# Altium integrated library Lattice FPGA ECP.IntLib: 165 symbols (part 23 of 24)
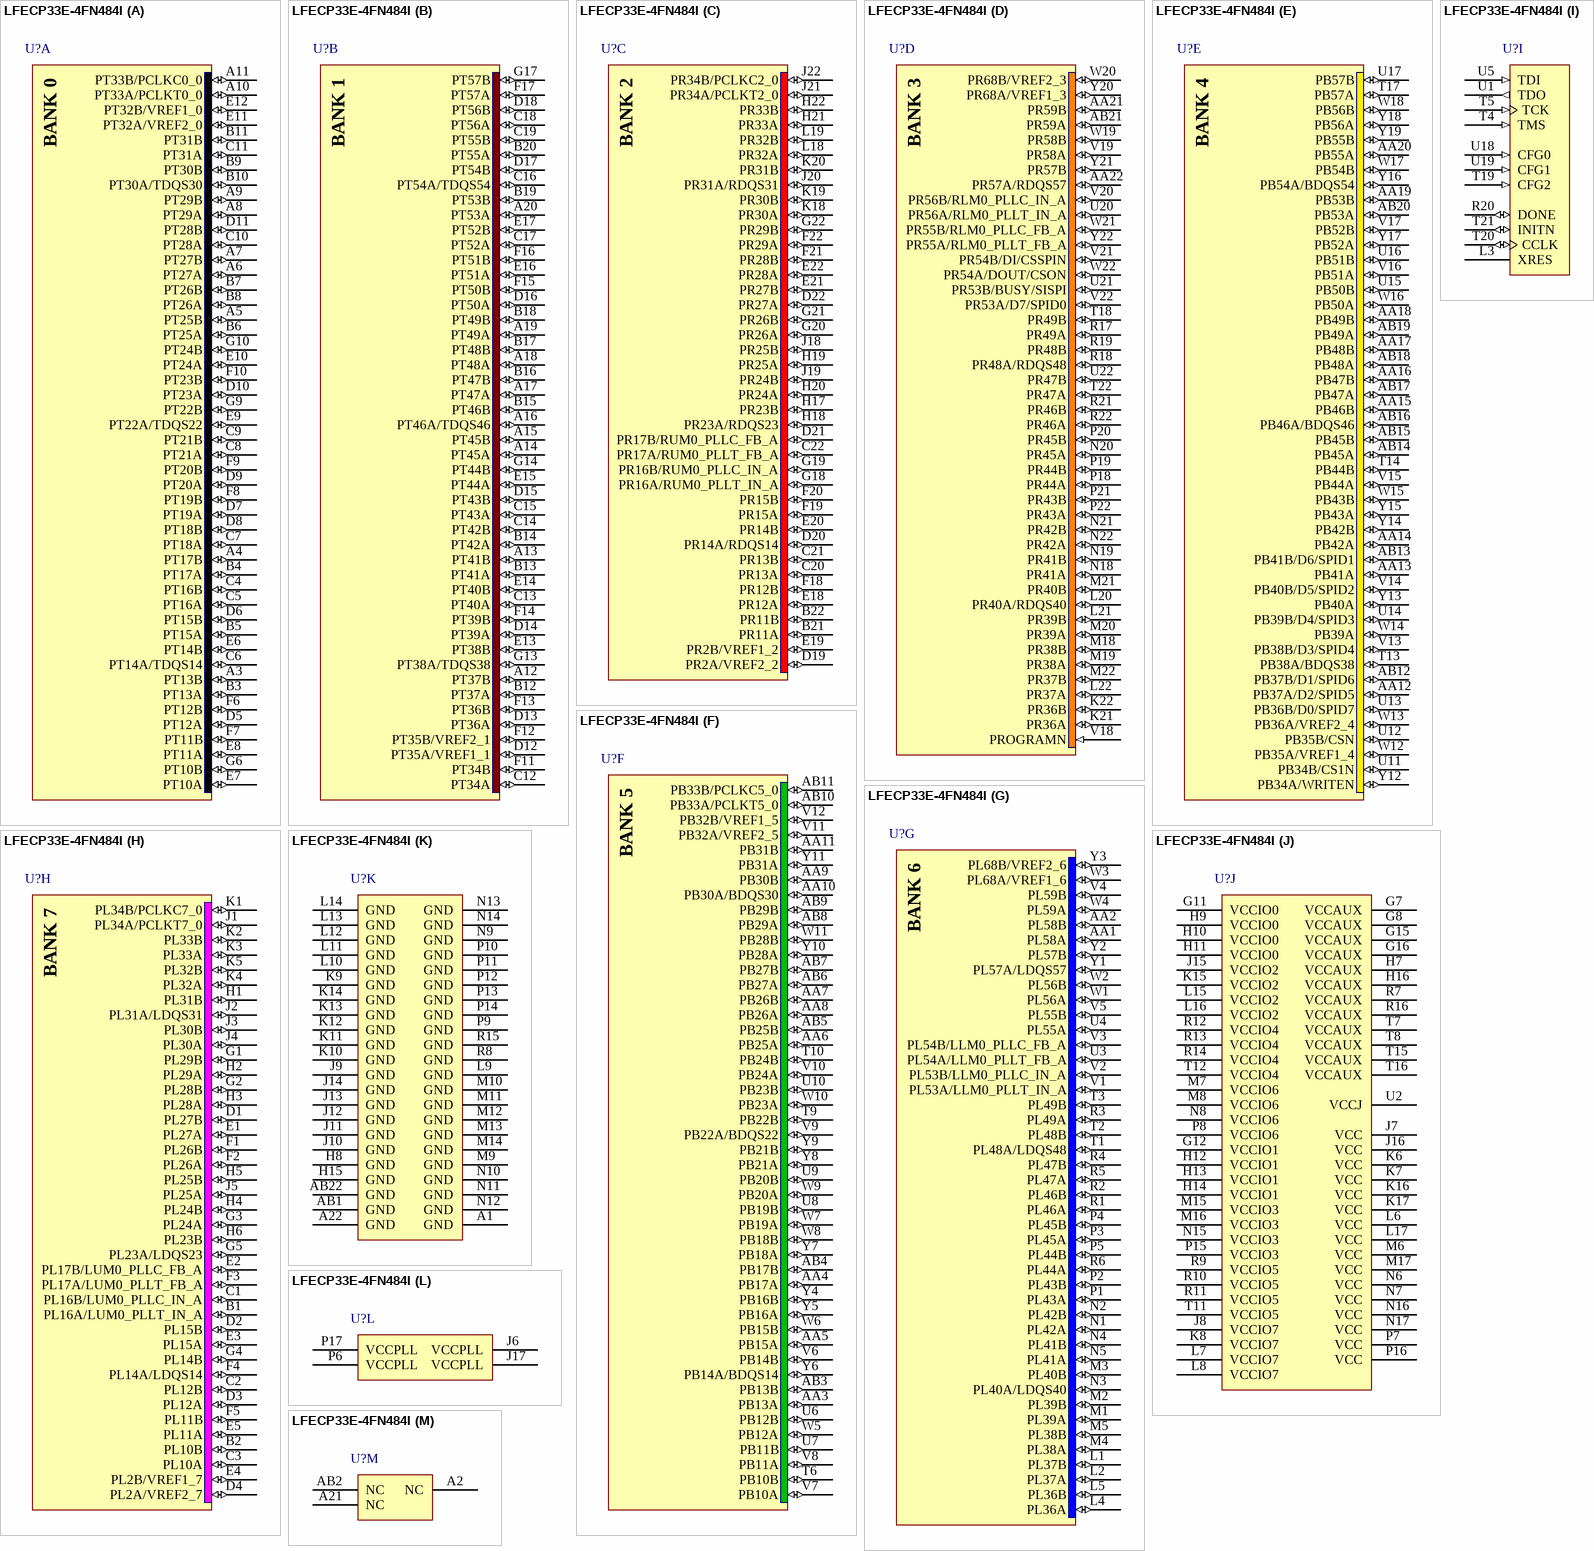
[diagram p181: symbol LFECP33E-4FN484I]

## LFECP33E-4FN484I
designator U?
ECP 1.2V FPGA, 360 I/Os, 4 PLLs, 32.8K LUTs, 8 sysDSP Blocks, 32 18x18 Multipliers, 484-Pin fpBGA, Pb-Free, Speed Grade 4, Industrial Temperature Grade
footprint fpBGA484 (BGA, 484-Leads, Body 23x23mm, Pitch 1mm)
3D model ECP33E-fpBGA484 (484-Ball Fine Pitch Ball Grid Array (fpBGA484))
part A pins: A3 PT13B (io), A4 PT17B (io), A5 PT25B (io), A6 PT27A (io), A7 PT27B (io), A8 PT29A (io), A9 PT29B (io), A10 PT33A/PCLKT0_0 (io), A11 PT33B/PCLKC0_0 (io), B3 PT13A (io), B4 PT17A (io), B5 PT15A (io), B6 PT25A (io), B7 PT26B (io), B8 PT26A (io), B9 PT30B (io), B10 PT30A/TDQS30 (io), B11 PT31B (io), C4 PT16B (io), C5 PT16A (io), C6 PT14A/TDQS14 (io), C7 PT18A (io), C8 PT21A (io), C9 PT21B (io), C10 PT28A (io), C11 PT31A (io), D5 PT12A (io), D6 PT15B (io), D7 PT19A (io), D8 PT18B (io), D9 PT20A (io), D10 PT23A (io), D11 PT28B (io), E6 PT14B (io), E7 PT10A (io), E8 PT11A (io), E9 PT22A/TDQS22 (io), E10 PT24A (io), E11 PT32A/VREF2_0 (io), E12 PT32B/VREF1_0 (io), F6 PT12B (io), F7 PT11B (io), F8 PT19B (io), F9 PT20B (io), F10 PT23B (io), G6 PT10B (io), G9 PT22B (io), G10 PT24B (io)
part B pins: A12 PT37B (io), A13 PT41B (io), A14 PT45A (io), A15 PT45B (io), A16 PT46A/TDQS46 (io), A17 PT47A (io), A18 PT48A (io), A19 PT49A (io), A20 PT53A (io), B12 PT37A (io), B13 PT41A (io), B14 PT42A (io), B15 PT46B (io), B16 PT47B (io), B17 PT48B (io), B18 PT49B (io), B19 PT53B (io), B20 PT55A (io), C12 PT34A (io), C13 PT40A (io), C14 PT42B (io), C15 PT43A (io), C16 PT54A/TDQS54 (io), C17 PT52A (io), C18 PT56A (io), C19 PT55B (io), D12 PT35A/VREF1_1 (io), D13 PT36A (io), D14 PT39A (io), D15 PT43B (io), D16 PT50A (io), D17 PT54B (io), D18 PT56B (io), E13 PT38B (io), E14 PT40B (io), E15 PT44A (io), E16 PT51A (io), E17 PT52B (io), F11 PT34B (io), F12 PT35B/VREF2_1 (io), F13 PT36B (io), F14 PT39B (io), F15 PT50B (io), F16 PT51B (io), F17 PT57A (io), G13 PT38A/TDQS38 (io), G14 PT44B (io), G17 PT57B (io)
part C pins: B21 PR11A (io), B22 PR11B (io), C20 PR13A (io), C21 PR13B (io), C22 PR17A/RUM0_PLLT_FB_A (io), D19 PR2A/VREF2_2 (io), D20 PR14A/RDQS14 (io), D21 PR17B/RUM0_PLLC_FB_A (io), D22 PR27A (io), E18 PR12A (io), E19 PR2B/VREF1_2 (io), E20 PR14B (io), E21 PR27B (io), E22 PR28A (io), F18 PR12B (io), F19 PR15A (io), F20 PR15B (io), F21 PR28B (io), F22 PR29A (io), G18 PR16A/RUM0_PLLT_IN_A (io), G19 PR16B/RUM0_PLLC_IN_A (io), G20 PR26A (io), G21 PR26B (io), G22 PR29B (io), H17 PR23B (io), H18 PR23A/RDQS23 (io), H19 PR25A (io), H20 PR24A (io), H21 PR33A (io), H22 PR33B (io), J18 PR25B (io), J19 PR24B (io), J20 PR31A/RDQS31 (io), J21 PR34A/PCLKT2_0 (io), J22 PR34B/PCLKC2_0 (io), K18 PR30A (io), K19 PR30B (io), K20 PR31B (io), L18 PR32A (io), L19 PR32B (io)
part D pins: AA21 PR59B (io), AA22 PR57A/RDQS57 (io), AB21 PR59A (io), K21 PR36A (io), K22 PR36B (io), L20 PR40A/RDQS40 (io), L21 PR39B (io), L22 PR37A (io), M18 PR38B (io), M19 PR38A (io), M20 PR39A (io), M21 PR40B (io), M22 PR37B (io), N18 PR41A (io), N19 PR41B (io), N20 PR45A (io), N21 PR42B (io), N22 PR42A (io), P18 PR44A (io), P19 PR44B (io), P20 PR45B (io), P21 PR43B (io), P22 PR43A (io), R17 PR49A (io), R18 PR48A/RDQS48 (io), R19 PR48B (io), R21 PR46B (io), R22 PR46A (io), T18 PR49B (io), T22 PR47A (io), U20 PR56A/RLM0_PLLT_IN_A (io), U21 PR53B/BUSY/SISPI (io), U22 PR47B (io), V18 PROGRAMN (in), V19 PR58A (io), V20 PR56B/RLM0_PLLC_IN_A (io), V21 PR54B/DI/CSSPIN (io), V22 PR53A/D7/SPID0 (io), W19 PR58B (io), W20 PR68B/VREF2_3 (io), W21 PR55B/RLM0_PLLC_FB_A (io), W22 PR54A/DOUT/CSON (io), Y20 PR68A/VREF1_3 (io), Y21 PR57B (io), Y22 PR55A/RLM0_PLLT_FB_A (io)
part E pins: AA12 PB37A/D2/SPID5 (io), AA13 PB41A (io), AA14 PB42A (io), AA15 PB46B (io), AA16 PB47B (io), AA17 PB48B (io), AA18 PB49B (io), AA19 PB53B (io), AA20 PB55A (io), AB12 PB37B/D1/SPID6 (io), AB13 PB41B/D6/SPID1 (io), AB14 PB45A (io), AB15 PB45B (io), AB16 PB46A/BDQS46 (io), AB17 PB47A (io), AB18 PB48A (io), AB19 PB49A (io), AB20 PB53A (io), T13 PB38A/BDQS38 (io), T14 PB44B (io), T17 PB57A (io), U11 PB34B/CS1N (io), U12 PB35B/CSN (io), U13 PB36B/D0/SPID7 (io), U14 PB39B/D4/SPID3 (io), U15 PB50B (io), U16 PB51B (io), U17 PB57B (io), V13 PB38B/D3/SPID4 (io), V14 PB40B/D5/SPID2 (io), V15 PB44A (io), V16 PB51A (io), V17 PB52B (io), W12 PB35A/VREF1_4 (io), W13 PB36A/VREF2_4 (io), W14 PB39A (io), W15 PB43B (io), W16 PB50A (io), W17 PB54B (io), W18 PB56B (io), Y12 PB34A/WRITEN (io), Y13 PB40A (io), Y14 PB42B (io), Y15 PB43A (io), Y16 PB54A/BDQS54 (io), Y17 PB52A (io), Y18 PB56A (io), Y19 PB55B (io)
part F pins: AA3 PB13A (io), AA4 PB17A (io), AA5 PB15A (io), AA6 PB25A (io), AA7 PB26B (io), AA8 PB26A (io), AA9 PB30B (io), AA10 PB30A/BDQS30 (io), AA11 PB31B (io), AB3 PB13B (io), AB4 PB17B (io), AB5 PB25B (io), AB6 PB27A (io), AB7 PB27B (io), AB8 PB29A (io), AB9 PB29B (io), AB10 PB33A/PCLKT5_0 (io), AB11 PB33B/PCLKC5_0 (io), T6 PB10B (io), T9 PB22B (io), T10 PB24B (io), U6 PB12B (io), U7 PB11B (io), U8 PB19B (io), U9 PB20B (io), U10 PB23B (io), V6 PB14B (io), V7 PB10A (io), V8 PB11A (io), V9 PB22A/BDQS22 (io), V10 PB24A (io), V11 PB32A/VREF2_5 (io), V12 PB32B/VREF1_5 (io), W5 PB12A (io), W6 PB15B (io), W7 PB19A (io), W8 PB18B (io), W9 PB20A (io), W10 PB23A (io), W11 PB28B (io), Y4 PB16B (io), Y5 PB16A (io), Y6 PB14A/BDQS14 (io), Y7 PB18A (io), Y8 PB21A (io), Y9 PB21B (io), Y10 PB28A (io), Y11 PB31A (io)
part G pins: AA1 PL58A (io), AA2 PL58B (io), L1 PL37B (io), L2 PL37A (io), L4 PL36A (io), L5 PL36B (io), M1 PL39A (io), M2 PL39B (io), M3 PL40B (io), M4 PL38A (io), M5 PL38B (io), N1 PL42A (io), N2 PL42B (io), N3 PL40A/LDQS40 (io), N4 PL41B (io), N5 PL41A (io), P1 PL43A (io), P2 PL43B (io), P3 PL45A (io), P4 PL45B (io), P5 PL44B (io), R1 PL46A (io), R2 PL46B (io), R3 PL49A (io), R4 PL47B (io), R5 PL47A (io), R6 PL44A (io), T1 PL48A/LDQS48 (io), T2 PL48B (io), T3 PL49B (io), U3 PL54A/LLM0_PLLT_FB_A (io), U4 PL55A (io), V1 PL53A/LLM0_PLLT_IN_A (io), V2 PL53B/LLM0_PLLC_IN_A (io), V3 PL54B/LLM0_PLLC_FB_A (io), V4 PL59B (io), V5 PL55B (io), W1 PL56A (io), W2 PL56B (io), W3 PL68A/VREF1_6 (io), W4 PL59A (io), Y1 PL57A/LDQS57 (io), Y2 PL57B (io), Y3 PL68B/VREF2_6 (io)
part H pins: B1 PL16A/LUM0_PLLT_IN_A (io), B2 PL10B (io), C1 PL16B/LUM0_PLLC_IN_A (io), C2 PL12B (io), C3 PL10A (io), D1 PL27B (io), D2 PL15B (io), D3 PL12A (io), D4 PL2A/VREF2_7 (io), E1 PL27A (io), E2 PL17B/LUM0_PLLC_FB_A (io), E3 PL15A (io), E4 PL2B/VREF1_7 (io), E5 PL11A (io), F1 PL26B (io), F2 PL26A (io), F3 PL17A/LUM0_PLLT_FB_A (io), F4 PL14A/LDQS14 (io), F5 PL11B (io), G1 PL29B (io), G2 PL28B (io), G3 PL24A (io), G4 PL14B (io), G5 PL23A/LDQS23 (io), H1 PL31B (io), H2 PL29A (io), H3 PL28A (io), H4 PL24B (io), H5 PL25B (io), H6 PL23B (io), J1 PL34A/PCLKT7_0 (io), J2 PL31A/LDQS31 (io), J3 PL30B (io), J4 PL30A (io), J5 PL25A (io), K1 PL34B/PCLKC7_0 (io), K2 PL33B (io), K3 PL33A (io), K4 PL32A (io), K5 PL32B (io)
part I pins: L3 XRES, R20 DONE (io), T4 TMS (in), T5 TCK (in), T19 CFG2 (in), T20 CCLK (io), T21 INITN (io), U1 TDO (out), U5 TDI (in), U18 CFG0 (in), U19 CFG1 (in)
part J pins: G7 VCCAUX (power), G8 VCCAUX (power), G11 VCCIO0 (power), G12 VCCIO1 (power), G15 VCCAUX (power), G16 VCCAUX (power), H7 VCCAUX (power), H9 VCCIO0 (power), H10 VCCIO0 (power), H11 VCCIO0 (power), H12 VCCIO1 (power), H13 VCCIO1 (power), H14 VCCIO1 (power), H16 VCCAUX (power), J7 VCC (power), J8 VCCIO7 (power), J15 VCCIO2 (power), J16 VCC (power), K6 VCC (power), K7 VCC (power), K8 VCCIO7 (power), K15 VCCIO2 (power), K16 VCC (power), K17 VCC (power), L6 VCC (power), L7 VCCIO7 (power), L8 VCCIO7 (power), L15 VCCIO2 (power), L16 VCCIO2 (power), L17 VCC (power), M6 VCC (power), M7 VCCIO6 (power), M8 VCCIO6 (power), M15 VCCIO3 (power), M16 VCCIO3 (power), M17 VCC (power), N6 VCC (power), N7 VCC (power), N8 VCCIO6 (power), N15 VCCIO3 (power), N16 VCC (power), N17 VCC (power), P7 VCC (power), P8 VCCIO6 (power), P15 VCCIO3 (power), P16 VCC (power), R7 VCCAUX (power), R9 VCCIO5 (power), R10 VCCIO5 (power), R11 VCCIO5 (power), R12 VCCIO4 (power), R13 VCCIO4 (power), R14 VCCIO4 (power), R16 VCCAUX (power), T7 VCCAUX (power), T8 VCCAUX (power), T11 VCCIO5 (power), T12 VCCIO4 (power), T15 VCCAUX (power), T16 VCCAUX (power), U2 VCCJ (power)
part K pins: A1 GND (power), A22 GND (power), AB1 GND (power), AB22 GND (power), H8 GND (power), H15 GND (power), J9 GND (power), J10 GND (power), J11 GND (power), J12 GND (power), J13 GND (power), J14 GND (power), K9 GND (power), K10 GND (power), K11 GND (power), K12 GND (power), K13 GND (power), K14 GND (power), L9 GND (power), L10 GND (power), L11 GND (power), L12 GND (power), L13 GND (power), L14 GND (power), M9 GND (power), M10 GND (power), M11 GND (power), M12 GND (power), M13 GND (power), M14 GND (power), N9 GND (power), N10 GND (power), N11 GND (power), N12 GND (power), N13 GND (power), N14 GND (power), P9 GND (power), P10 GND (power), P11 GND (power), P12 GND (power), P13 GND (power), P14 GND (power), R8 GND (power), R15 GND (power)
part L pins: J6 VCCPLL (power), J17 VCCPLL (power), P6 VCCPLL (power), P17 VCCPLL (power)
part M pins: A2 NC, A21 NC, AB2 NC

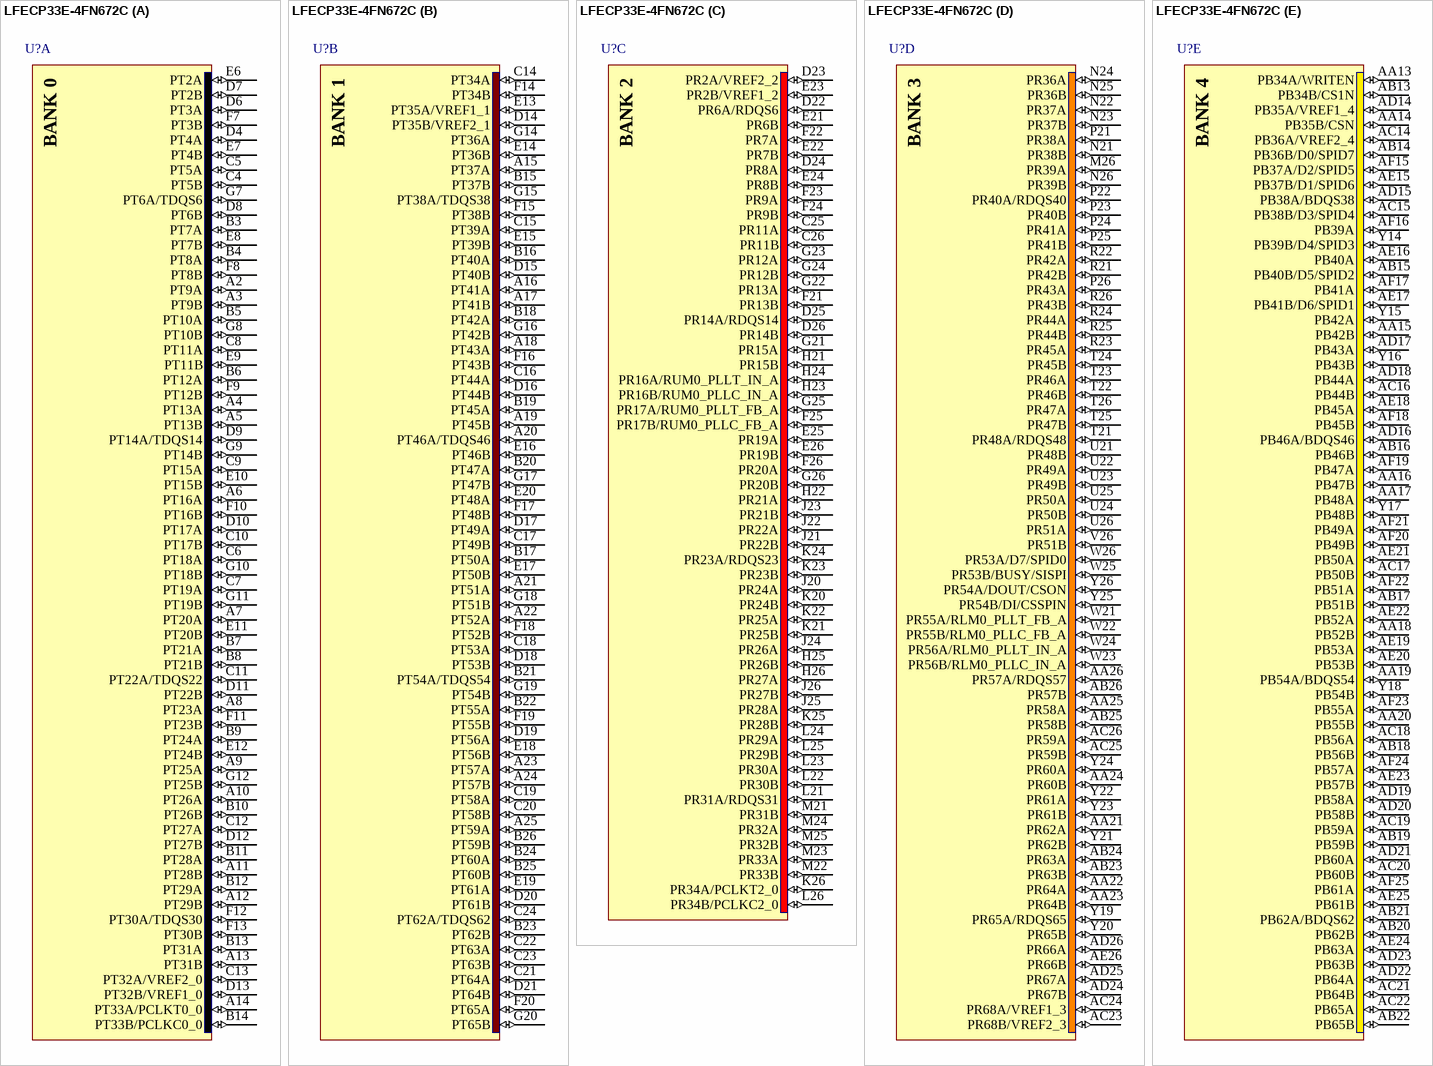
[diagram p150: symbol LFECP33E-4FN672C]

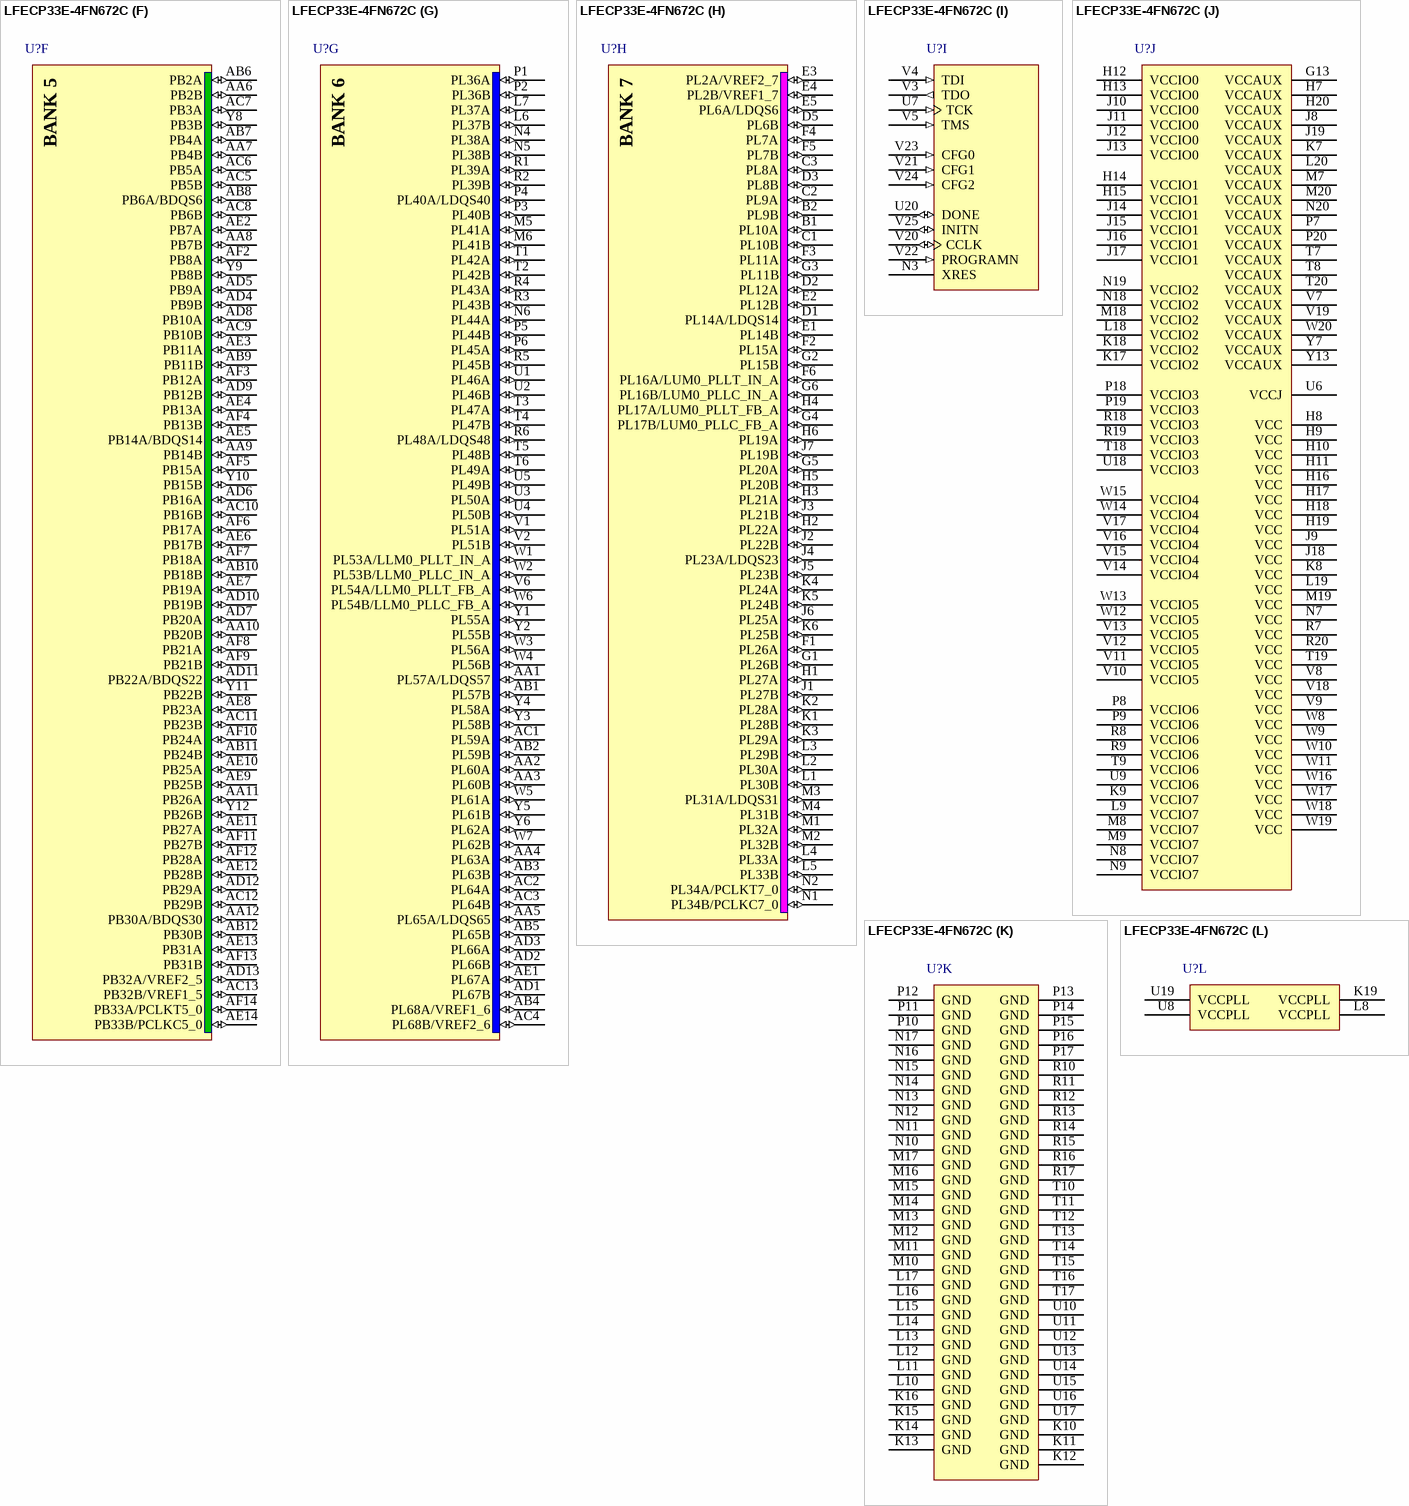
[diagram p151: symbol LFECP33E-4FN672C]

## LFECP33E-4FN672C
designator U?
ECP 1.2V FPGA, 496 I/Os, 4 PLLs, 32.8K LUTs, 8 sysDSP Blocks, 32 18x18 Multipliers, 672-Pin fpBGA, Pb-Free, Speed Grade 4, Commercial Temperature Grade
footprint fpBGA672 (BGA, 672-Leads, Body 27x27mm, Pitch 1mm)
3D model ECP33E-fpBGA672 (672-Ball Fine Pitch Ball Grid Array (fpBGA672))
part A pins: A2 PT9A (io), A3 PT9B (io), A4 PT13A (io), A5 PT13B (io), A6 PT16A (io), A7 PT20A (io), A8 PT23A (io), A9 PT25A (io), A10 PT26A (io), A11 PT28B (io), A12 PT29B (io), A13 PT31B (io), A14 PT33A/PCLKT0_0 (io), B3 PT7A (io), B4 PT8A (io), B5 PT10A (io), B6 PT12A (io), B7 PT21A (io), B8 PT21B (io), B9 PT24A (io), B10 PT26B (io), B11 PT28A (io), B12 PT29A (io), B13 PT31A (io), B14 PT33B/PCLKC0_0 (io), C4 PT5B (io), C5 PT5A (io), C6 PT18A (io), C7 PT19A (io), C8 PT11A (io), C9 PT15A (io), C10 PT17B (io), C11 PT22A/TDQS22 (io), C12 PT27A (io), C13 PT32A/VREF2_0 (io), D4 PT4A (io), D6 PT3A (io), D7 PT2B (io), D8 PT6B (io), D9 PT14A/TDQS14 (io), D10 PT17A (io), D11 PT22B (io), D12 PT27B (io), D13 PT32B/VREF1_0 (io), E6 PT2A (io), E7 PT4B (io), E8 PT7B (io), E9 PT11B (io), E10 PT15B (io), E11 PT20B (io), E12 PT24B (io), F7 PT3B (io), F8 PT8B (io), F9 PT12B (io), F10 PT16B (io), F11 PT23B (io), F12 PT30A/TDQS30 (io), F13 PT30B (io), G7 PT6A/TDQS6 (io), G8 PT10B (io), G9 PT14B (io), G10 PT18B (io), G11 PT19B (io), G12 PT25B (io)
part B pins: A15 PT37A (io), A16 PT41A (io), A17 PT41B (io), A18 PT43A (io), A19 PT45B (io), A20 PT46A/TDQS46 (io), A21 PT51A (io), A22 PT52A (io), A23 PT57A (io), A24 PT57B (io), A25 PT59A (io), B15 PT37B (io), B16 PT40A (io), B17 PT50A (io), B18 PT42A (io), B19 PT45A (io), B20 PT47A (io), B21 PT54A/TDQS54 (io), B22 PT55A (io), B23 PT62B (io), B24 PT60A (io), B25 PT60B (io), B26 PT59B (io), C14 PT34A (io), C15 PT39A (io), C16 PT44A (io), C17 PT49B (io), C18 PT53A (io), C19 PT58A (io), C20 PT58B (io), C21 PT64A (io), C22 PT63A (io), C23 PT63B (io), C24 PT62A/TDQS62 (io), D14 PT35B/VREF2_1 (io), D15 PT40B (io), D16 PT44B (io), D17 PT49A (io), D18 PT53B (io), D19 PT56A (io), D20 PT61B (io), D21 PT64B (io), E13 PT35A/VREF1_1 (io), E14 PT36B (io), E15 PT39B (io), E16 PT46B (io), E17 PT50B (io), E18 PT56B (io), E19 PT61A (io), E20 PT48A (io), F14 PT34B (io), F15 PT38B (io), F16 PT43B (io), F17 PT48B (io), F18 PT52B (io), F19 PT55B (io), F20 PT65A (io), G14 PT36A (io), G15 PT38A/TDQS38 (io), G16 PT42B (io), G17 PT47B (io), G18 PT51B (io), G19 PT54B (io), G20 PT65B (io)
part C pins: C25 PR11A (io), C26 PR11B (io), D22 PR6A/RDQS6 (io), D23 PR2A/VREF2_2 (io), D24 PR8A (io), D25 PR14A/RDQS14 (io), D26 PR14B (io), E21 PR6B (io), E22 PR7B (io), E23 PR2B/VREF1_2 (io), E24 PR8B (io), E25 PR19A (io), E26 PR19B (io), F21 PR13B (io), F22 PR7A (io), F23 PR9A (io), F24 PR9B (io), F25 PR17B/RUM0_PLLC_FB_A (io), F26 PR20A (io), G21 PR15A (io), G22 PR13A (io), G23 PR12A (io), G24 PR12B (io), G25 PR17A/RUM0_PLLT_FB_A (io), G26 PR20B (io), H21 PR15B (io), H22 PR21A (io), H23 PR16B/RUM0_PLLC_IN_A (io), H24 PR16A/RUM0_PLLT_IN_A (io), H25 PR26B (io), H26 PR27A (io), J20 PR24A (io), J21 PR22B (io), J22 PR22A (io), J23 PR21B (io), J24 PR26A (io), J25 PR28A (io), J26 PR27B (io), K20 PR24B (io), K21 PR25B (io), K22 PR25A (io), K23 PR23B (io), K24 PR23A/RDQS23 (io), K25 PR28B (io), K26 PR34A/PCLKT2_0 (io), L21 PR31A/RDQS31 (io), L22 PR30B (io), L23 PR30A (io), L24 PR29A (io), L25 PR29B (io), L26 PR34B/PCLKC2_0 (io), M21 PR31B (io), M22 PR33B (io), M23 PR33A (io), M24 PR32A (io), M25 PR32B (io)
part D pins: AA21 PR62A (io), AA22 PR64A (io), AA23 PR64B (io), AA24 PR60B (io), AA25 PR58A (io), AA26 PR57A/RDQS57 (io), AB23 PR63B (io), AB24 PR63A (io), AB25 PR58B (io), AB26 PR57B (io), AC23 PR68B/VREF2_3 (io), AC24 PR68A/VREF1_3 (io), AC25 PR59B (io), AC26 PR59A (io), AD24 PR67B (io), AD25 PR67A (io), AD26 PR66A (io), AE26 PR66B (io), M26 PR39A (io), N21 PR38B (io), N22 PR37A (io), N23 PR37B (io), N24 PR36A (io), N25 PR36B (io), N26 PR39B (io), P21 PR38A (io), P22 PR40A/RDQS40 (io), P23 PR40B (io), P24 PR41A (io), P25 PR41B (io), P26 PR43A (io), R21 PR42B (io), R22 PR42A (io), R23 PR45A (io), R24 PR44A (io), R25 PR44B (io), R26 PR43B (io), T21 PR48A/RDQS48 (io), T22 PR46B (io), T23 PR46A (io), T24 PR45B (io), T25 PR47B (io), T26 PR47A (io), U21 PR48B (io), U22 PR49A (io), U23 PR49B (io), U24 PR50B (io), U25 PR50A (io), U26 PR51A (io), V26 PR51B (io), W21 PR55A/RLM0_PLLT_FB_A (io), W22 PR55B/RLM0_PLLC_FB_A (io), W23 PR56B/RLM0_PLLC_IN_A (io), W24 PR56A/RLM0_PLLT_IN_A (io), W25 PR53B/BUSY/SISPI (io), W26 PR53A/D7/SPID0 (io), Y19 PR65A/RDQS65 (io), Y20 PR65B (io), Y21 PR62B (io), Y22 PR61A (io), Y23 PR61B (io), Y24 PR60A (io), Y25 PR54B/DI/CSSPIN (io), Y26 PR54A/DOUT/CSON (io)
part E pins: AA13 PB34A/WRITEN (io), AA14 PB35B/CSN (io), AA15 PB42B (io), AA16 PB47B (io), AA17 PB48A (io), AA18 PB52B (io), AA19 PB54A/BDQS54 (io), AA20 PB55B (io), AB13 PB34B/CS1N (io), AB14 PB36B/D0/SPID7 (io), AB15 PB40B/D5/SPID2 (io), AB16 PB46B (io), AB17 PB51B (io), AB18 PB56B (io), AB19 PB59B (io), AB20 PB62B (io), AB21 PB62A/BDQS62 (io), AB22 PB65B (io), AC14 PB36A/VREF2_4 (io), AC15 PB38B/D3/SPID4 (io), AC16 PB44B (io), AC17 PB50B (io), AC18 PB56A (io), AC19 PB59A (io), AC20 PB60B (io), AC21 PB64B (io), AC22 PB65A (io), AD14 PB35A/VREF1_4 (io), AD15 PB38A/BDQS38 (io), AD16 PB46A/BDQS46 (io), AD17 PB43A (io), AD18 PB44A (io), AD19 PB58A (io), AD20 PB58B (io), AD21 PB60A (io), AD22 PB64A (io), AD23 PB63B (io), AE15 PB37B/D1/SPID6 (io), AE16 PB40A (io), AE17 PB41B/D6/SPID1 (io), AE18 PB45A (io), AE19 PB53A (io), AE20 PB53B (io), AE21 PB50A (io), AE22 PB52A (io), AE23 PB57B (io), AE24 PB63A (io), AE25 PB61B (io), AF15 PB37A/D2/SPID5 (io), AF16 PB39A (io), AF17 PB41A (io), AF18 PB45B (io), AF19 PB47A (io), AF20 PB49B (io), AF21 PB49A (io), AF22 PB51A (io), AF23 PB55A (io), AF24 PB57A (io), AF25 PB61A (io), Y14 PB39B/D4/SPID3 (io), Y15 PB42A (io), Y16 PB43B (io), Y17 PB48B (io), Y18 PB54B (io)
part F pins: AA6 PB2B (io), AA7 PB4B (io), AA8 PB7B (io), AA9 PB14B (io), AA10 PB20B (io), AA11 PB26A (io), AA12 PB30A/BDQS30 (io), AB6 PB2A (io), AB7 PB4A (io), AB8 PB6A/BDQS6 (io), AB9 PB11B (io), AB10 PB18B (io), AB11 PB24B (io), AB12 PB30B (io), AC5 PB5B (io), AC6 PB5A (io), AC7 PB3A (io), AC8 PB6B (io), AC9 PB10B (io), AC10 PB16B (io), AC11 PB23B (io), AC12 PB29B (io), AC13 PB32B/VREF1_5 (io), AD4 PB9B (io), AD5 PB9A (io), AD6 PB16A (io), AD7 PB20A (io), AD8 PB10A (io), AD9 PB12B (io), AD10 PB19B (io), AD11 PB22A/BDQS22 (io), AD12 PB29A (io), AD13 PB32A/VREF2_5 (io), AE2 PB7A (io), AE3 PB11A (io), AE4 PB13A (io), AE5 PB14A/BDQS14 (io), AE6 PB17B (io), AE7 PB19A (io), AE8 PB23A (io), AE9 PB25B (io), AE10 PB25A (io), AE11 PB27A (io), AE12 PB28B (io), AE13 PB31A (io), AE14 PB33B/PCLKC5_0 (io), AF2 PB8A (io), AF3 PB12A (io), AF4 PB13B (io), AF5 PB15A (io), AF6 PB17A (io), AF7 PB18A (io), AF8 PB21A (io), AF9 PB21B (io), AF10 PB24A (io), AF11 PB27B (io), AF12 PB28A (io), AF13 PB31B (io), AF14 PB33A/PCLKT5_0 (io), Y8 PB3B (io), Y9 PB8B (io), Y10 PB15B (io), Y11 PB22B (io), Y12 PB26B (io)
part G pins: AA1 PL57A/LDQS57 (io), AA2 PL60A (io), AA3 PL60B (io), AA4 PL63A (io), AA5 PL65A/LDQS65 (io), AB1 PL57B (io), AB2 PL59B (io), AB3 PL63B (io), AB4 PL68A/VREF1_6 (io), AB5 PL65B (io), AC1 PL59A (io), AC2 PL64A (io), AC3 PL64B (io), AC4 PL68B/VREF2_6 (io), AD1 PL67B (io), AD2 PL66B (io), AD3 PL66A (io), AE1 PL67A (io), L6 PL37B (io), L7 PL37A (io), M5 PL41A (io), M6 PL41B (io), N4 PL38A (io), N5 PL38B (io), N6 PL44A (io), P1 PL36A (io), P2 PL36B (io), P3 PL40B (io), P4 PL40A/LDQS40 (io), P5 PL44B (io), P6 PL45A (io), R1 PL39A (io), R2 PL39B (io), R3 PL43B (io), R4 PL43A (io), R5 PL45B (io), R6 PL48A/LDQS48 (io), T1 PL42A (io), T2 PL42B (io), T3 PL47A (io), T4 PL47B (io), T5 PL48B (io), T6 PL49A (io), U1 PL46A (io), U2 PL46B (io), U3 PL50A (io), U4 PL50B (io), U5 PL49B (io), V1 PL51A (io), V2 PL51B (io), V6 PL54A/LLM0_PLLT_FB_A (io), W1 PL53A/LLM0_PLLT_IN_A (io), W2 PL53B/LLM0_PLLC_IN_A (io), W3 PL56A (io), W4 PL56B (io), W5 PL61A (io), W6 PL54B/LLM0_PLLC_FB_A (io), W7 PL62B (io), Y1 PL55A (io), Y2 PL55B (io), Y3 PL58B (io), Y4 PL58A (io), Y5 PL61B (io), Y6 PL62A (io)
part H pins: B1 PL10A (io), B2 PL9B (io), C1 PL10B (io), C2 PL9A (io), C3 PL8A (io), D1 PL14A/LDQS14 (io), D2 PL12A (io), D3 PL8B (io), D5 PL6B (io), E1 PL14B (io), E2 PL12B (io), E3 PL2A/VREF2_7 (io), E4 PL2B/VREF1_7 (io), E5 PL6A/LDQS6 (io), F1 PL26A (io), F2 PL15A (io), F3 PL11A (io), F4 PL7A (io), F5 PL7B (io), F6 PL16A/LUM0_PLLT_IN_A (io), G1 PL26B (io), G2 PL15B (io), G3 PL11B (io), G4 PL17B/LUM0_PLLC_FB_A (io), G5 PL20A (io), G6 PL16B/LUM0_PLLC_IN_A (io), H1 PL27A (io), H2 PL22A (io), H3 PL21A (io), H4 PL17A/LUM0_PLLT_FB_A (io), H5 PL20B (io), H6 PL19A (io), J1 PL27B (io), J2 PL22B (io), J3 PL21B (io), J4 PL23A/LDQS23 (io), J5 PL23B (io), J6 PL25A (io), J7 PL19B (io), K1 PL28B (io), K2 PL28A (io), K3 PL29A (io), K4 PL24A (io), K5 PL24B (io), K6 PL25B (io), L1 PL30B (io), L2 PL30A (io), L3 PL29B (io), L4 PL33A (io), L5 PL33B (io), M1 PL32A (io), M2 PL32B (io), M3 PL31A/LDQS31 (io), M4 PL31B (io), N1 PL34B/PCLKC7_0 (io), N2 PL34A/PCLKT7_0 (io)
part I pins: N3 XRES, U7 TCK (in), U20 DONE (io), V3 TDO (out), V4 TDI (in), V5 TMS (in), V20 CCLK (io), V21 CFG1 (in), V22 PROGRAMN (in), V23 CFG0 (in), V24 CFG2 (in), V25 INITN (io)
part J pins: G13 VCCAUX (power), H7 VCCAUX (power), H8 VCC (power), H9 VCC (power), H10 VCC (power), H11 VCC (power), H12 VCCIO0 (power), H13 VCCIO0 (power), H14 VCCIO1 (power), H15 VCCIO1 (power), H16 VCC (power), H17 VCC (power), H18 VCC (power), H19 VCC (power), H20 VCCAUX (power), J8 VCCAUX (power), J9 VCC (power), J10 VCCIO0 (power), J11 VCCIO0 (power), J12 VCCIO0 (power), J13 VCCIO0 (power), J14 VCCIO1 (power), J15 VCCIO1 (power), J16 VCCIO1 (power), J17 VCCIO1 (power), J18 VCC (power), J19 VCCAUX (power), K7 VCCAUX (power), K8 VCC (power), K9 VCCIO7 (power), K17 VCCIO2 (power), K18 VCCIO2 (power), L9 VCCIO7 (power), L18 VCCIO2 (power), L19 VCC (power), L20 VCCAUX (power), M7 VCCAUX (power), M8 VCCIO7 (power), M9 VCCIO7 (power), M18 VCCIO2 (power), M19 VCC (power), M20 VCCAUX (power), N7 VCC (power), N8 VCCIO7 (power), N9 VCCIO7 (power), N18 VCCIO2 (power), N19 VCCIO2 (power), N20 VCCAUX (power), P7 VCCAUX (power), P8 VCCIO6 (power), P9 VCCIO6 (power), P18 VCCIO3 (power), P19 VCCIO3 (power), P20 VCCAUX (power), R7 VCC (power), R8 VCCIO6 (power), R9 VCCIO6 (power), R18 VCCIO3 (power), R19 VCCIO3 (power), R20 VCC (power), T7 VCCAUX (power), T8 VCCAUX (power), T9 VCCIO6 (power), T18 VCCIO3 (power), T19 VCC (power), T20 VCCAUX (power), U6 VCCJ (power), U9 VCCIO6 (power), U18 VCCIO3 (power), V7 VCCAUX (power), V8 VCC (power), V9 VCC (power), V10 VCCIO5 (power), V11 VCCIO5 (power), V12 VCCIO5 (power), V13 VCCIO5 (power), V14 VCCIO4 (power), V15 VCCIO4 (power), V16 VCCIO4 (power), V17 VCCIO4 (power), V18 VCC (power), V19 VCCAUX (power), W8 VCC (power), W9 VCC (power), W10 VCC (power), W11 VCC (power), W12 VCCIO5 (power), W13 VCCIO5 (power), W14 VCCIO4 (power), W15 VCCIO4 (power), W16 VCC (power), W17 VCC (power), W18 VCC (power), W19 VCC (power), W20 VCCAUX (power), Y7 VCCAUX (power), Y13 VCCAUX (power)
part K pins: K10 GND (power), K11 GND (power), K12 GND (power), K13 GND (power), K14 GND (power), K15 GND (power), K16 GND (power), L10 GND (power), L11 GND (power), L12 GND (power), L13 GND (power), L14 GND (power), L15 GND (power), L16 GND (power), L17 GND (power), M10 GND (power), M11 GND (power), M12 GND (power), M13 GND (power), M14 GND (power), M15 GND (power), M16 GND (power), M17 GND (power), N10 GND (power), N11 GND (power), N12 GND (power), N13 GND (power), N14 GND (power), N15 GND (power), N16 GND (power), N17 GND (power), P10 GND (power), P11 GND (power), P12 GND (power), P13 GND (power), P14 GND (power), P15 GND (power), P16 GND (power), P17 GND (power), R10 GND (power), R11 GND (power), R12 GND (power), R13 GND (power), R14 GND (power), R15 GND (power), R16 GND (power), R17 GND (power), T10 GND (power), T11 GND (power), T12 GND (power), T13 GND (power), T14 GND (power), T15 GND (power), T16 GND (power), T17 GND (power), U10 GND (power), U11 GND (power), U12 GND (power), U13 GND (power), U14 GND (power), U15 GND (power), U16 GND (power), U17 GND (power)
part L pins: K19 VCCPLL (power), L8 VCCPLL (power), U8 VCCPLL (power), U19 VCCPLL (power)

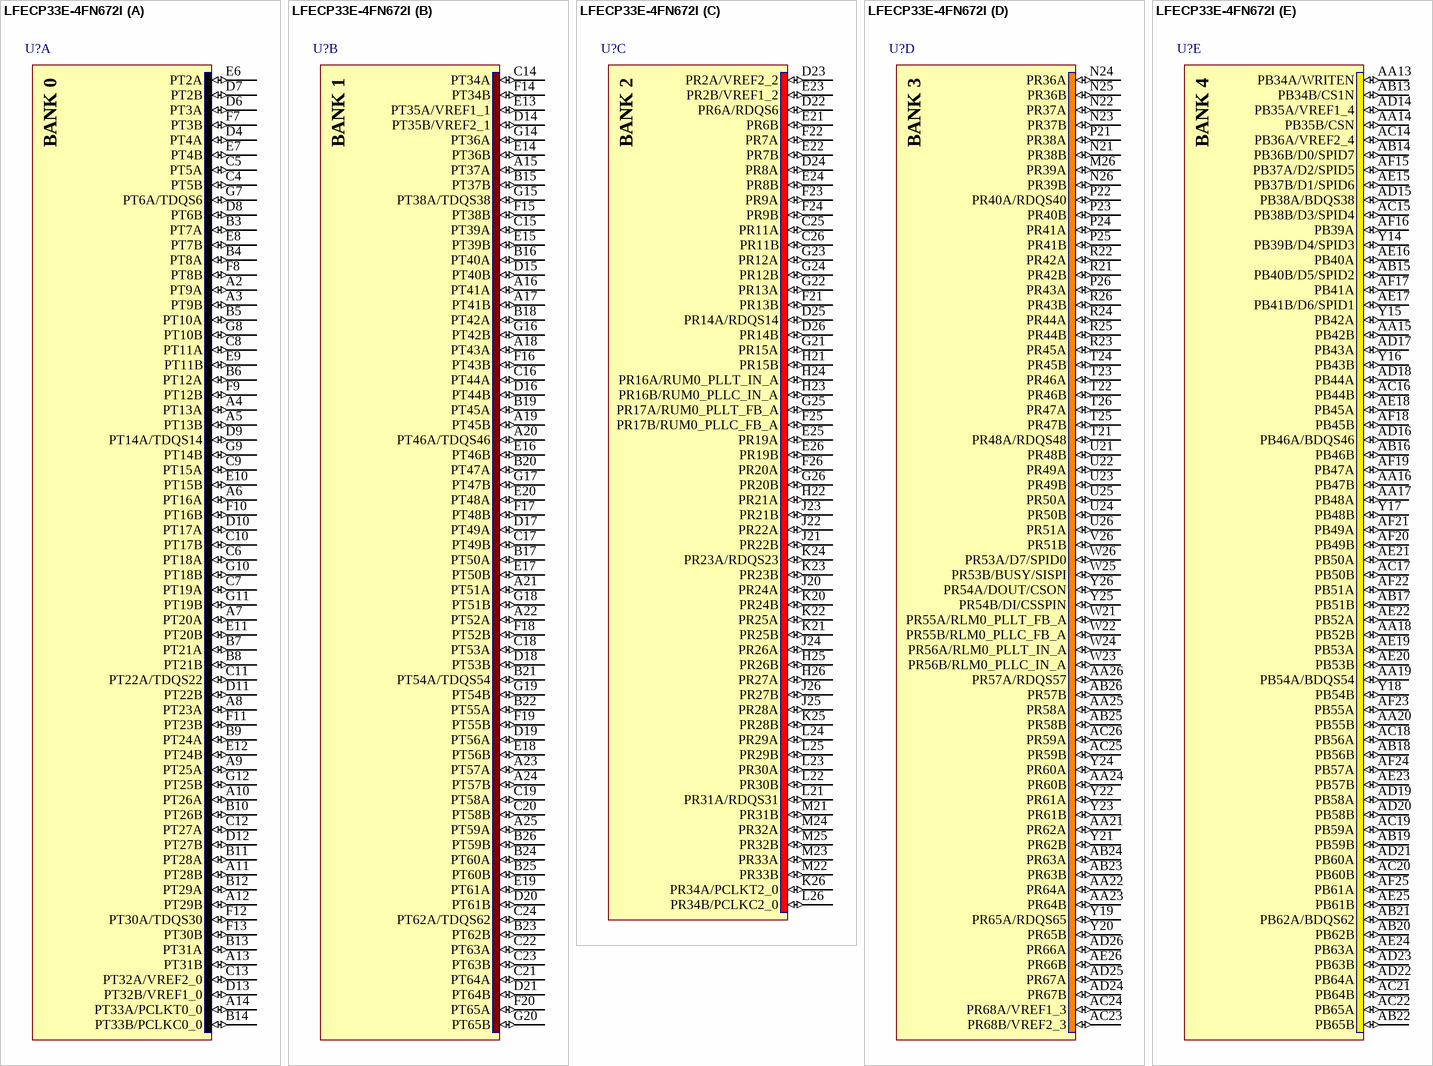
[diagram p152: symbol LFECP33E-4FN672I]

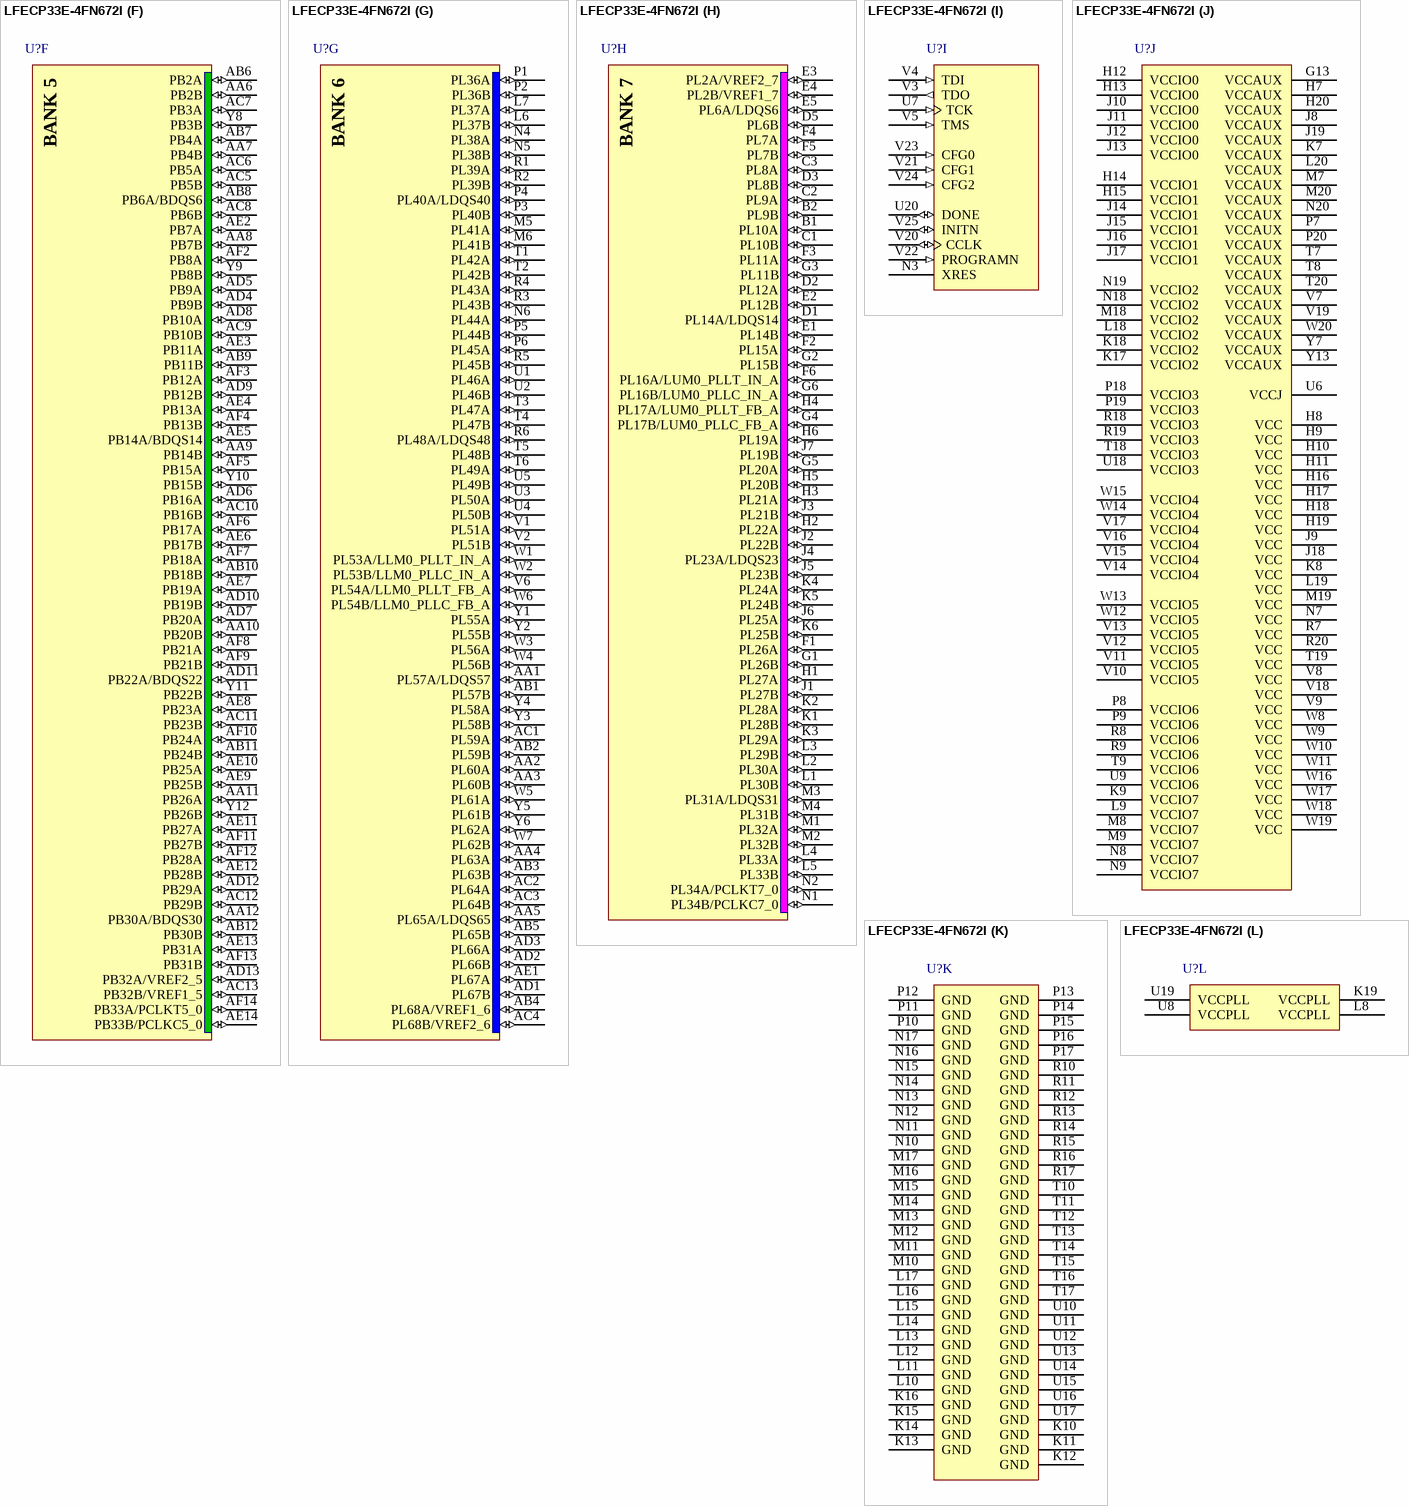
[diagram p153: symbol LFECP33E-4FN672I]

## LFECP33E-4FN672I
designator U?
ECP 1.2V FPGA, 496 I/Os, 4 PLLs, 32.8K LUTs, 8 sysDSP Blocks, 32 18x18 Multipliers, 672-Pin fpBGA, Pb-Free, Speed Grade 4, Industrial Temperature Grade
footprint fpBGA672 (BGA, 672-Leads, Body 27x27mm, Pitch 1mm)
3D model ECP33E-fpBGA672 (672-Ball Fine Pitch Ball Grid Array (fpBGA672))
part A pins: A2 PT9A (io), A3 PT9B (io), A4 PT13A (io), A5 PT13B (io), A6 PT16A (io), A7 PT20A (io), A8 PT23A (io), A9 PT25A (io), A10 PT26A (io), A11 PT28B (io), A12 PT29B (io), A13 PT31B (io), A14 PT33A/PCLKT0_0 (io), B3 PT7A (io), B4 PT8A (io), B5 PT10A (io), B6 PT12A (io), B7 PT21A (io), B8 PT21B (io), B9 PT24A (io), B10 PT26B (io), B11 PT28A (io), B12 PT29A (io), B13 PT31A (io), B14 PT33B/PCLKC0_0 (io), C4 PT5B (io), C5 PT5A (io), C6 PT18A (io), C7 PT19A (io), C8 PT11A (io), C9 PT15A (io), C10 PT17B (io), C11 PT22A/TDQS22 (io), C12 PT27A (io), C13 PT32A/VREF2_0 (io), D4 PT4A (io), D6 PT3A (io), D7 PT2B (io), D8 PT6B (io), D9 PT14A/TDQS14 (io), D10 PT17A (io), D11 PT22B (io), D12 PT27B (io), D13 PT32B/VREF1_0 (io), E6 PT2A (io), E7 PT4B (io), E8 PT7B (io), E9 PT11B (io), E10 PT15B (io), E11 PT20B (io), E12 PT24B (io), F7 PT3B (io), F8 PT8B (io), F9 PT12B (io), F10 PT16B (io), F11 PT23B (io), F12 PT30A/TDQS30 (io), F13 PT30B (io), G7 PT6A/TDQS6 (io), G8 PT10B (io), G9 PT14B (io), G10 PT18B (io), G11 PT19B (io), G12 PT25B (io)
part B pins: A15 PT37A (io), A16 PT41A (io), A17 PT41B (io), A18 PT43A (io), A19 PT45B (io), A20 PT46A/TDQS46 (io), A21 PT51A (io), A22 PT52A (io), A23 PT57A (io), A24 PT57B (io), A25 PT59A (io), B15 PT37B (io), B16 PT40A (io), B17 PT50A (io), B18 PT42A (io), B19 PT45A (io), B20 PT47A (io), B21 PT54A/TDQS54 (io), B22 PT55A (io), B23 PT62B (io), B24 PT60A (io), B25 PT60B (io), B26 PT59B (io), C14 PT34A (io), C15 PT39A (io), C16 PT44A (io), C17 PT49B (io), C18 PT53A (io), C19 PT58A (io), C20 PT58B (io), C21 PT64A (io), C22 PT63A (io), C23 PT63B (io), C24 PT62A/TDQS62 (io), D14 PT35B/VREF2_1 (io), D15 PT40B (io), D16 PT44B (io), D17 PT49A (io), D18 PT53B (io), D19 PT56A (io), D20 PT61B (io), D21 PT64B (io), E13 PT35A/VREF1_1 (io), E14 PT36B (io), E15 PT39B (io), E16 PT46B (io), E17 PT50B (io), E18 PT56B (io), E19 PT61A (io), E20 PT48A (io), F14 PT34B (io), F15 PT38B (io), F16 PT43B (io), F17 PT48B (io), F18 PT52B (io), F19 PT55B (io), F20 PT65A (io), G14 PT36A (io), G15 PT38A/TDQS38 (io), G16 PT42B (io), G17 PT47B (io), G18 PT51B (io), G19 PT54B (io), G20 PT65B (io)
part C pins: C25 PR11A (io), C26 PR11B (io), D22 PR6A/RDQS6 (io), D23 PR2A/VREF2_2 (io), D24 PR8A (io), D25 PR14A/RDQS14 (io), D26 PR14B (io), E21 PR6B (io), E22 PR7B (io), E23 PR2B/VREF1_2 (io), E24 PR8B (io), E25 PR19A (io), E26 PR19B (io), F21 PR13B (io), F22 PR7A (io), F23 PR9A (io), F24 PR9B (io), F25 PR17B/RUM0_PLLC_FB_A (io), F26 PR20A (io), G21 PR15A (io), G22 PR13A (io), G23 PR12A (io), G24 PR12B (io), G25 PR17A/RUM0_PLLT_FB_A (io), G26 PR20B (io), H21 PR15B (io), H22 PR21A (io), H23 PR16B/RUM0_PLLC_IN_A (io), H24 PR16A/RUM0_PLLT_IN_A (io), H25 PR26B (io), H26 PR27A (io), J20 PR24A (io), J21 PR22B (io), J22 PR22A (io), J23 PR21B (io), J24 PR26A (io), J25 PR28A (io), J26 PR27B (io), K20 PR24B (io), K21 PR25B (io), K22 PR25A (io), K23 PR23B (io), K24 PR23A/RDQS23 (io), K25 PR28B (io), K26 PR34A/PCLKT2_0 (io), L21 PR31A/RDQS31 (io), L22 PR30B (io), L23 PR30A (io), L24 PR29A (io), L25 PR29B (io), L26 PR34B/PCLKC2_0 (io), M21 PR31B (io), M22 PR33B (io), M23 PR33A (io), M24 PR32A (io), M25 PR32B (io)
part D pins: AA21 PR62A (io), AA22 PR64A (io), AA23 PR64B (io), AA24 PR60B (io), AA25 PR58A (io), AA26 PR57A/RDQS57 (io), AB23 PR63B (io), AB24 PR63A (io), AB25 PR58B (io), AB26 PR57B (io), AC23 PR68B/VREF2_3 (io), AC24 PR68A/VREF1_3 (io), AC25 PR59B (io), AC26 PR59A (io), AD24 PR67B (io), AD25 PR67A (io), AD26 PR66A (io), AE26 PR66B (io), M26 PR39A (io), N21 PR38B (io), N22 PR37A (io), N23 PR37B (io), N24 PR36A (io), N25 PR36B (io), N26 PR39B (io), P21 PR38A (io), P22 PR40A/RDQS40 (io), P23 PR40B (io), P24 PR41A (io), P25 PR41B (io), P26 PR43A (io), R21 PR42B (io), R22 PR42A (io), R23 PR45A (io), R24 PR44A (io), R25 PR44B (io), R26 PR43B (io), T21 PR48A/RDQS48 (io), T22 PR46B (io), T23 PR46A (io), T24 PR45B (io), T25 PR47B (io), T26 PR47A (io), U21 PR48B (io), U22 PR49A (io), U23 PR49B (io), U24 PR50B (io), U25 PR50A (io), U26 PR51A (io), V26 PR51B (io), W21 PR55A/RLM0_PLLT_FB_A (io), W22 PR55B/RLM0_PLLC_FB_A (io), W23 PR56B/RLM0_PLLC_IN_A (io), W24 PR56A/RLM0_PLLT_IN_A (io), W25 PR53B/BUSY/SISPI (io), W26 PR53A/D7/SPID0 (io), Y19 PR65A/RDQS65 (io), Y20 PR65B (io), Y21 PR62B (io), Y22 PR61A (io), Y23 PR61B (io), Y24 PR60A (io), Y25 PR54B/DI/CSSPIN (io), Y26 PR54A/DOUT/CSON (io)
part E pins: AA13 PB34A/WRITEN (io), AA14 PB35B/CSN (io), AA15 PB42B (io), AA16 PB47B (io), AA17 PB48A (io), AA18 PB52B (io), AA19 PB54A/BDQS54 (io), AA20 PB55B (io), AB13 PB34B/CS1N (io), AB14 PB36B/D0/SPID7 (io), AB15 PB40B/D5/SPID2 (io), AB16 PB46B (io), AB17 PB51B (io), AB18 PB56B (io), AB19 PB59B (io), AB20 PB62B (io), AB21 PB62A/BDQS62 (io), AB22 PB65B (io), AC14 PB36A/VREF2_4 (io), AC15 PB38B/D3/SPID4 (io), AC16 PB44B (io), AC17 PB50B (io), AC18 PB56A (io), AC19 PB59A (io), AC20 PB60B (io), AC21 PB64B (io), AC22 PB65A (io), AD14 PB35A/VREF1_4 (io), AD15 PB38A/BDQS38 (io), AD16 PB46A/BDQS46 (io), AD17 PB43A (io), AD18 PB44A (io), AD19 PB58A (io), AD20 PB58B (io), AD21 PB60A (io), AD22 PB64A (io), AD23 PB63B (io), AE15 PB37B/D1/SPID6 (io), AE16 PB40A (io), AE17 PB41B/D6/SPID1 (io), AE18 PB45A (io), AE19 PB53A (io), AE20 PB53B (io), AE21 PB50A (io), AE22 PB52A (io), AE23 PB57B (io), AE24 PB63A (io), AE25 PB61B (io), AF15 PB37A/D2/SPID5 (io), AF16 PB39A (io), AF17 PB41A (io), AF18 PB45B (io), AF19 PB47A (io), AF20 PB49B (io), AF21 PB49A (io), AF22 PB51A (io), AF23 PB55A (io), AF24 PB57A (io), AF25 PB61A (io), Y14 PB39B/D4/SPID3 (io), Y15 PB42A (io), Y16 PB43B (io), Y17 PB48B (io), Y18 PB54B (io)
part F pins: AA6 PB2B (io), AA7 PB4B (io), AA8 PB7B (io), AA9 PB14B (io), AA10 PB20B (io), AA11 PB26A (io), AA12 PB30A/BDQS30 (io), AB6 PB2A (io), AB7 PB4A (io), AB8 PB6A/BDQS6 (io), AB9 PB11B (io), AB10 PB18B (io), AB11 PB24B (io), AB12 PB30B (io), AC5 PB5B (io), AC6 PB5A (io), AC7 PB3A (io), AC8 PB6B (io), AC9 PB10B (io), AC10 PB16B (io), AC11 PB23B (io), AC12 PB29B (io), AC13 PB32B/VREF1_5 (io), AD4 PB9B (io), AD5 PB9A (io), AD6 PB16A (io), AD7 PB20A (io), AD8 PB10A (io), AD9 PB12B (io), AD10 PB19B (io), AD11 PB22A/BDQS22 (io), AD12 PB29A (io), AD13 PB32A/VREF2_5 (io), AE2 PB7A (io), AE3 PB11A (io), AE4 PB13A (io), AE5 PB14A/BDQS14 (io), AE6 PB17B (io), AE7 PB19A (io), AE8 PB23A (io), AE9 PB25B (io), AE10 PB25A (io), AE11 PB27A (io), AE12 PB28B (io), AE13 PB31A (io), AE14 PB33B/PCLKC5_0 (io), AF2 PB8A (io), AF3 PB12A (io), AF4 PB13B (io), AF5 PB15A (io), AF6 PB17A (io), AF7 PB18A (io), AF8 PB21A (io), AF9 PB21B (io), AF10 PB24A (io), AF11 PB27B (io), AF12 PB28A (io), AF13 PB31B (io), AF14 PB33A/PCLKT5_0 (io), Y8 PB3B (io), Y9 PB8B (io), Y10 PB15B (io), Y11 PB22B (io), Y12 PB26B (io)
part G pins: AA1 PL57A/LDQS57 (io), AA2 PL60A (io), AA3 PL60B (io), AA4 PL63A (io), AA5 PL65A/LDQS65 (io), AB1 PL57B (io), AB2 PL59B (io), AB3 PL63B (io), AB4 PL68A/VREF1_6 (io), AB5 PL65B (io), AC1 PL59A (io), AC2 PL64A (io), AC3 PL64B (io), AC4 PL68B/VREF2_6 (io), AD1 PL67B (io), AD2 PL66B (io), AD3 PL66A (io), AE1 PL67A (io), L6 PL37B (io), L7 PL37A (io), M5 PL41A (io), M6 PL41B (io), N4 PL38A (io), N5 PL38B (io), N6 PL44A (io), P1 PL36A (io), P2 PL36B (io), P3 PL40B (io), P4 PL40A/LDQS40 (io), P5 PL44B (io), P6 PL45A (io), R1 PL39A (io), R2 PL39B (io), R3 PL43B (io), R4 PL43A (io), R5 PL45B (io), R6 PL48A/LDQS48 (io), T1 PL42A (io), T2 PL42B (io), T3 PL47A (io), T4 PL47B (io), T5 PL48B (io), T6 PL49A (io), U1 PL46A (io), U2 PL46B (io), U3 PL50A (io), U4 PL50B (io), U5 PL49B (io), V1 PL51A (io), V2 PL51B (io), V6 PL54A/LLM0_PLLT_FB_A (io), W1 PL53A/LLM0_PLLT_IN_A (io), W2 PL53B/LLM0_PLLC_IN_A (io), W3 PL56A (io), W4 PL56B (io), W5 PL61A (io), W6 PL54B/LLM0_PLLC_FB_A (io), W7 PL62B (io), Y1 PL55A (io), Y2 PL55B (io), Y3 PL58B (io), Y4 PL58A (io), Y5 PL61B (io), Y6 PL62A (io)
part H pins: B1 PL10A (io), B2 PL9B (io), C1 PL10B (io), C2 PL9A (io), C3 PL8A (io), D1 PL14A/LDQS14 (io), D2 PL12A (io), D3 PL8B (io), D5 PL6B (io), E1 PL14B (io), E2 PL12B (io), E3 PL2A/VREF2_7 (io), E4 PL2B/VREF1_7 (io), E5 PL6A/LDQS6 (io), F1 PL26A (io), F2 PL15A (io), F3 PL11A (io), F4 PL7A (io), F5 PL7B (io), F6 PL16A/LUM0_PLLT_IN_A (io), G1 PL26B (io), G2 PL15B (io), G3 PL11B (io), G4 PL17B/LUM0_PLLC_FB_A (io), G5 PL20A (io), G6 PL16B/LUM0_PLLC_IN_A (io), H1 PL27A (io), H2 PL22A (io), H3 PL21A (io), H4 PL17A/LUM0_PLLT_FB_A (io), H5 PL20B (io), H6 PL19A (io), J1 PL27B (io), J2 PL22B (io), J3 PL21B (io), J4 PL23A/LDQS23 (io), J5 PL23B (io), J6 PL25A (io), J7 PL19B (io), K1 PL28B (io), K2 PL28A (io), K3 PL29A (io), K4 PL24A (io), K5 PL24B (io), K6 PL25B (io), L1 PL30B (io), L2 PL30A (io), L3 PL29B (io), L4 PL33A (io), L5 PL33B (io), M1 PL32A (io), M2 PL32B (io), M3 PL31A/LDQS31 (io), M4 PL31B (io), N1 PL34B/PCLKC7_0 (io), N2 PL34A/PCLKT7_0 (io)
part I pins: N3 XRES, U7 TCK (in), U20 DONE (io), V3 TDO (out), V4 TDI (in), V5 TMS (in), V20 CCLK (io), V21 CFG1 (in), V22 PROGRAMN (in), V23 CFG0 (in), V24 CFG2 (in), V25 INITN (io)
part J pins: G13 VCCAUX (power), H7 VCCAUX (power), H8 VCC (power), H9 VCC (power), H10 VCC (power), H11 VCC (power), H12 VCCIO0 (power), H13 VCCIO0 (power), H14 VCCIO1 (power), H15 VCCIO1 (power), H16 VCC (power), H17 VCC (power), H18 VCC (power), H19 VCC (power), H20 VCCAUX (power), J8 VCCAUX (power), J9 VCC (power), J10 VCCIO0 (power), J11 VCCIO0 (power), J12 VCCIO0 (power), J13 VCCIO0 (power), J14 VCCIO1 (power), J15 VCCIO1 (power), J16 VCCIO1 (power), J17 VCCIO1 (power), J18 VCC (power), J19 VCCAUX (power), K7 VCCAUX (power), K8 VCC (power), K9 VCCIO7 (power), K17 VCCIO2 (power), K18 VCCIO2 (power), L9 VCCIO7 (power), L18 VCCIO2 (power), L19 VCC (power), L20 VCCAUX (power), M7 VCCAUX (power), M8 VCCIO7 (power), M9 VCCIO7 (power), M18 VCCIO2 (power), M19 VCC (power), M20 VCCAUX (power), N7 VCC (power), N8 VCCIO7 (power), N9 VCCIO7 (power), N18 VCCIO2 (power), N19 VCCIO2 (power), N20 VCCAUX (power), P7 VCCAUX (power), P8 VCCIO6 (power), P9 VCCIO6 (power), P18 VCCIO3 (power), P19 VCCIO3 (power), P20 VCCAUX (power), R7 VCC (power), R8 VCCIO6 (power), R9 VCCIO6 (power), R18 VCCIO3 (power), R19 VCCIO3 (power), R20 VCC (power), T7 VCCAUX (power), T8 VCCAUX (power), T9 VCCIO6 (power), T18 VCCIO3 (power), T19 VCC (power), T20 VCCAUX (power), U6 VCCJ (power), U9 VCCIO6 (power), U18 VCCIO3 (power), V7 VCCAUX (power), V8 VCC (power), V9 VCC (power), V10 VCCIO5 (power), V11 VCCIO5 (power), V12 VCCIO5 (power), V13 VCCIO5 (power), V14 VCCIO4 (power), V15 VCCIO4 (power), V16 VCCIO4 (power), V17 VCCIO4 (power), V18 VCC (power), V19 VCCAUX (power), W8 VCC (power), W9 VCC (power), W10 VCC (power), W11 VCC (power), W12 VCCIO5 (power), W13 VCCIO5 (power), W14 VCCIO4 (power), W15 VCCIO4 (power), W16 VCC (power), W17 VCC (power), W18 VCC (power), W19 VCC (power), W20 VCCAUX (power), Y7 VCCAUX (power), Y13 VCCAUX (power)
part K pins: K10 GND (power), K11 GND (power), K12 GND (power), K13 GND (power), K14 GND (power), K15 GND (power), K16 GND (power), L10 GND (power), L11 GND (power), L12 GND (power), L13 GND (power), L14 GND (power), L15 GND (power), L16 GND (power), L17 GND (power), M10 GND (power), M11 GND (power), M12 GND (power), M13 GND (power), M14 GND (power), M15 GND (power), M16 GND (power), M17 GND (power), N10 GND (power), N11 GND (power), N12 GND (power), N13 GND (power), N14 GND (power), N15 GND (power), N16 GND (power), N17 GND (power), P10 GND (power), P11 GND (power), P12 GND (power), P13 GND (power), P14 GND (power), P15 GND (power), P16 GND (power), P17 GND (power), R10 GND (power), R11 GND (power), R12 GND (power), R13 GND (power), R14 GND (power), R15 GND (power), R16 GND (power), R17 GND (power), T10 GND (power), T11 GND (power), T12 GND (power), T13 GND (power), T14 GND (power), T15 GND (power), T16 GND (power), T17 GND (power), U10 GND (power), U11 GND (power), U12 GND (power), U13 GND (power), U14 GND (power), U15 GND (power), U16 GND (power), U17 GND (power)
part L pins: K19 VCCPLL (power), L8 VCCPLL (power), U8 VCCPLL (power), U19 VCCPLL (power)

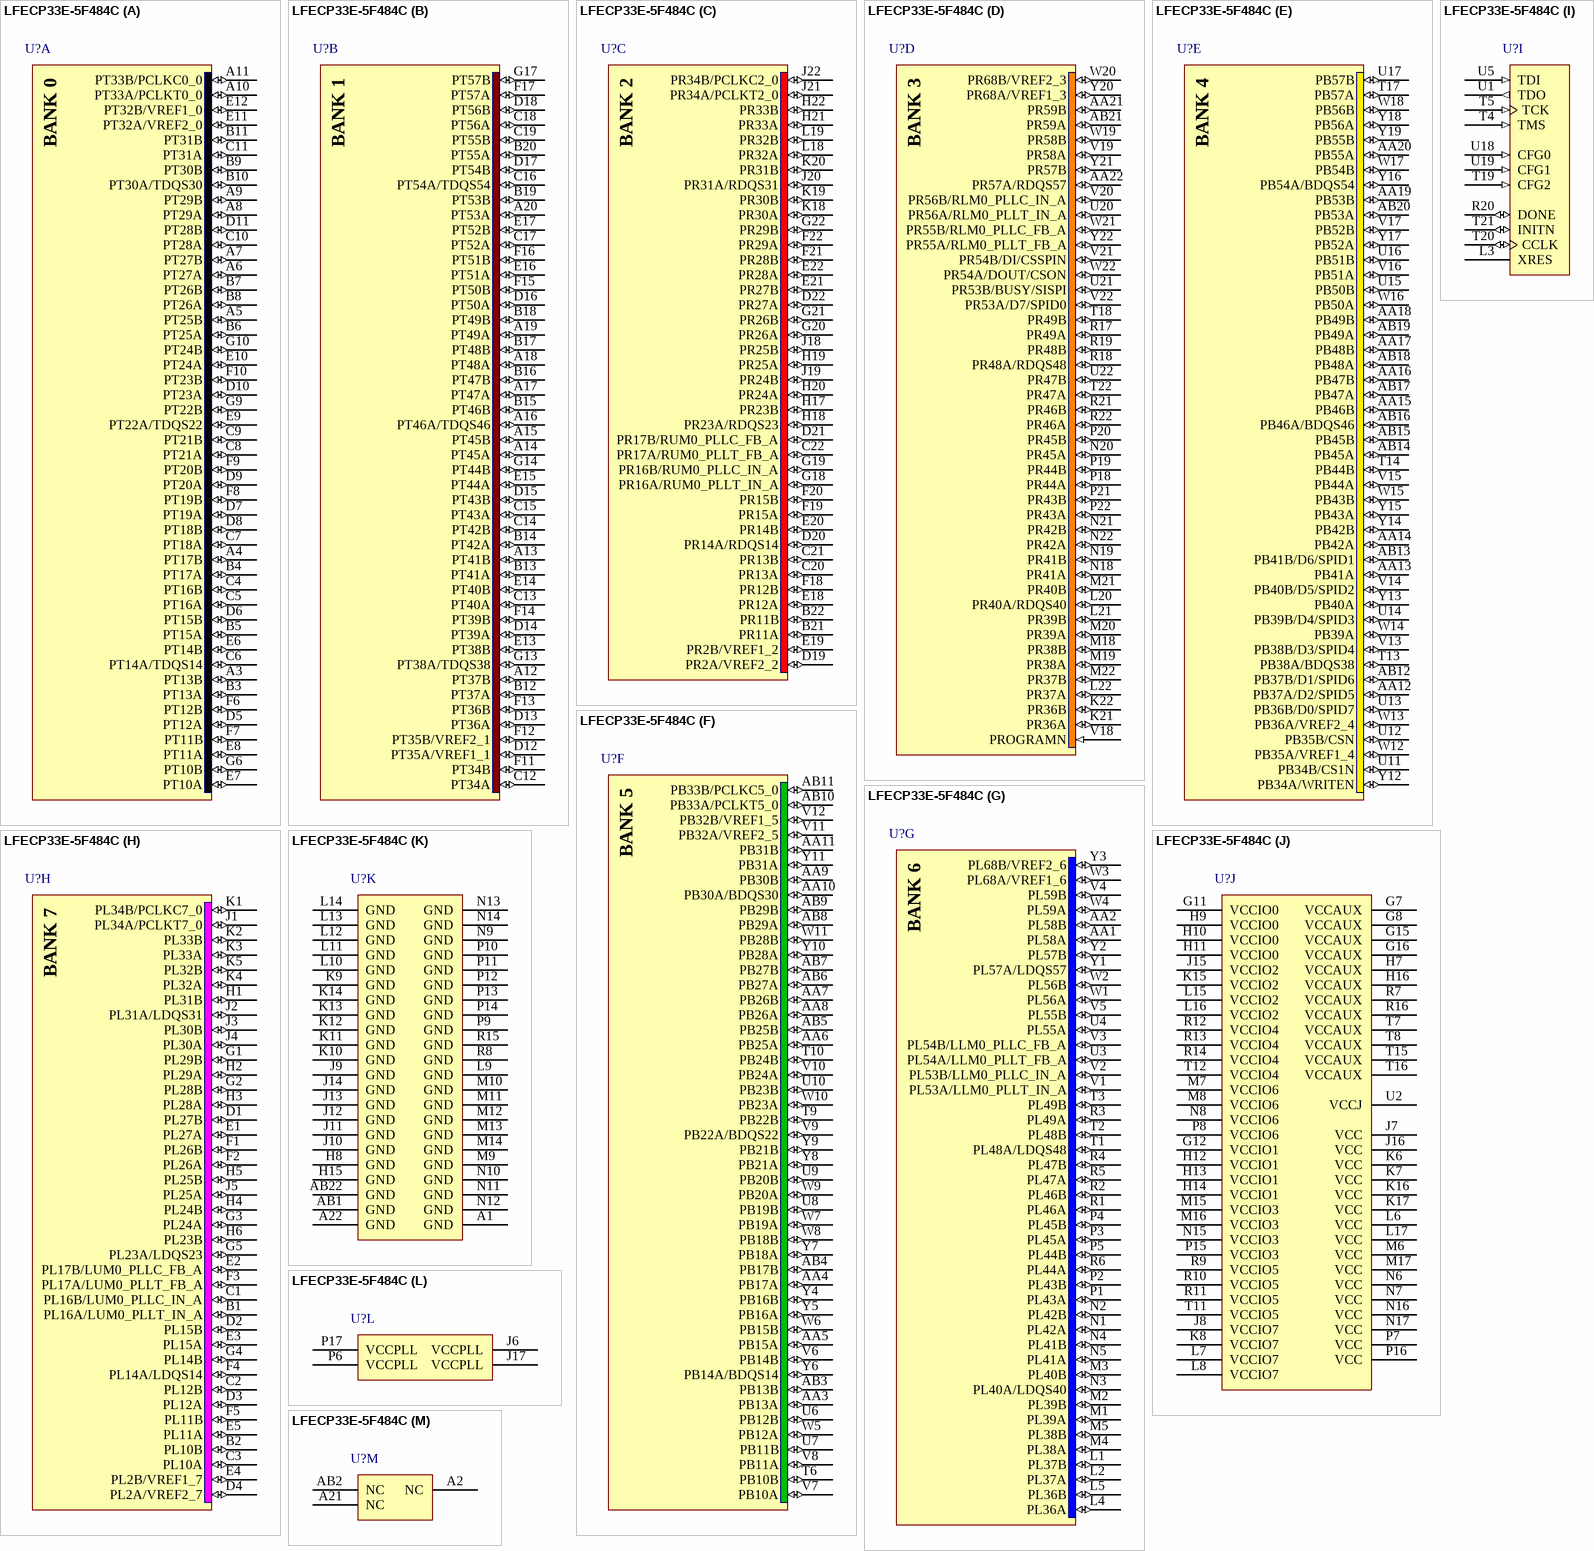
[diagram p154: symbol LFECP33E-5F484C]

## LFECP33E-5F484C
designator U?
ECP 1.2V FPGA, 360 I/Os, 4 PLLs, 32.8K LUTs, 8 sysDSP Blocks, 32 18x18 Multipliers, 484-Pin fpBGA, Speed Grade 5, Commercial Temperature Grade
footprint fpBGA484 (BGA, 484-Leads, Body 23x23mm, Pitch 1mm)
3D model ECP33E-fpBGA484 (484-Ball Fine Pitch Ball Grid Array (fpBGA484))
part A pins: A3 PT13B (io), A4 PT17B (io), A5 PT25B (io), A6 PT27A (io), A7 PT27B (io), A8 PT29A (io), A9 PT29B (io), A10 PT33A/PCLKT0_0 (io), A11 PT33B/PCLKC0_0 (io), B3 PT13A (io), B4 PT17A (io), B5 PT15A (io), B6 PT25A (io), B7 PT26B (io), B8 PT26A (io), B9 PT30B (io), B10 PT30A/TDQS30 (io), B11 PT31B (io), C4 PT16B (io), C5 PT16A (io), C6 PT14A/TDQS14 (io), C7 PT18A (io), C8 PT21A (io), C9 PT21B (io), C10 PT28A (io), C11 PT31A (io), D5 PT12A (io), D6 PT15B (io), D7 PT19A (io), D8 PT18B (io), D9 PT20A (io), D10 PT23A (io), D11 PT28B (io), E6 PT14B (io), E7 PT10A (io), E8 PT11A (io), E9 PT22A/TDQS22 (io), E10 PT24A (io), E11 PT32A/VREF2_0 (io), E12 PT32B/VREF1_0 (io), F6 PT12B (io), F7 PT11B (io), F8 PT19B (io), F9 PT20B (io), F10 PT23B (io), G6 PT10B (io), G9 PT22B (io), G10 PT24B (io)
part B pins: A12 PT37B (io), A13 PT41B (io), A14 PT45A (io), A15 PT45B (io), A16 PT46A/TDQS46 (io), A17 PT47A (io), A18 PT48A (io), A19 PT49A (io), A20 PT53A (io), B12 PT37A (io), B13 PT41A (io), B14 PT42A (io), B15 PT46B (io), B16 PT47B (io), B17 PT48B (io), B18 PT49B (io), B19 PT53B (io), B20 PT55A (io), C12 PT34A (io), C13 PT40A (io), C14 PT42B (io), C15 PT43A (io), C16 PT54A/TDQS54 (io), C17 PT52A (io), C18 PT56A (io), C19 PT55B (io), D12 PT35A/VREF1_1 (io), D13 PT36A (io), D14 PT39A (io), D15 PT43B (io), D16 PT50A (io), D17 PT54B (io), D18 PT56B (io), E13 PT38B (io), E14 PT40B (io), E15 PT44A (io), E16 PT51A (io), E17 PT52B (io), F11 PT34B (io), F12 PT35B/VREF2_1 (io), F13 PT36B (io), F14 PT39B (io), F15 PT50B (io), F16 PT51B (io), F17 PT57A (io), G13 PT38A/TDQS38 (io), G14 PT44B (io), G17 PT57B (io)
part C pins: B21 PR11A (io), B22 PR11B (io), C20 PR13A (io), C21 PR13B (io), C22 PR17A/RUM0_PLLT_FB_A (io), D19 PR2A/VREF2_2 (io), D20 PR14A/RDQS14 (io), D21 PR17B/RUM0_PLLC_FB_A (io), D22 PR27A (io), E18 PR12A (io), E19 PR2B/VREF1_2 (io), E20 PR14B (io), E21 PR27B (io), E22 PR28A (io), F18 PR12B (io), F19 PR15A (io), F20 PR15B (io), F21 PR28B (io), F22 PR29A (io), G18 PR16A/RUM0_PLLT_IN_A (io), G19 PR16B/RUM0_PLLC_IN_A (io), G20 PR26A (io), G21 PR26B (io), G22 PR29B (io), H17 PR23B (io), H18 PR23A/RDQS23 (io), H19 PR25A (io), H20 PR24A (io), H21 PR33A (io), H22 PR33B (io), J18 PR25B (io), J19 PR24B (io), J20 PR31A/RDQS31 (io), J21 PR34A/PCLKT2_0 (io), J22 PR34B/PCLKC2_0 (io), K18 PR30A (io), K19 PR30B (io), K20 PR31B (io), L18 PR32A (io), L19 PR32B (io)
part D pins: AA21 PR59B (io), AA22 PR57A/RDQS57 (io), AB21 PR59A (io), K21 PR36A (io), K22 PR36B (io), L20 PR40A/RDQS40 (io), L21 PR39B (io), L22 PR37A (io), M18 PR38B (io), M19 PR38A (io), M20 PR39A (io), M21 PR40B (io), M22 PR37B (io), N18 PR41A (io), N19 PR41B (io), N20 PR45A (io), N21 PR42B (io), N22 PR42A (io), P18 PR44A (io), P19 PR44B (io), P20 PR45B (io), P21 PR43B (io), P22 PR43A (io), R17 PR49A (io), R18 PR48A/RDQS48 (io), R19 PR48B (io), R21 PR46B (io), R22 PR46A (io), T18 PR49B (io), T22 PR47A (io), U20 PR56A/RLM0_PLLT_IN_A (io), U21 PR53B/BUSY/SISPI (io), U22 PR47B (io), V18 PROGRAMN (in), V19 PR58A (io), V20 PR56B/RLM0_PLLC_IN_A (io), V21 PR54B/DI/CSSPIN (io), V22 PR53A/D7/SPID0 (io), W19 PR58B (io), W20 PR68B/VREF2_3 (io), W21 PR55B/RLM0_PLLC_FB_A (io), W22 PR54A/DOUT/CSON (io), Y20 PR68A/VREF1_3 (io), Y21 PR57B (io), Y22 PR55A/RLM0_PLLT_FB_A (io)
part E pins: AA12 PB37A/D2/SPID5 (io), AA13 PB41A (io), AA14 PB42A (io), AA15 PB46B (io), AA16 PB47B (io), AA17 PB48B (io), AA18 PB49B (io), AA19 PB53B (io), AA20 PB55A (io), AB12 PB37B/D1/SPID6 (io), AB13 PB41B/D6/SPID1 (io), AB14 PB45A (io), AB15 PB45B (io), AB16 PB46A/BDQS46 (io), AB17 PB47A (io), AB18 PB48A (io), AB19 PB49A (io), AB20 PB53A (io), T13 PB38A/BDQS38 (io), T14 PB44B (io), T17 PB57A (io), U11 PB34B/CS1N (io), U12 PB35B/CSN (io), U13 PB36B/D0/SPID7 (io), U14 PB39B/D4/SPID3 (io), U15 PB50B (io), U16 PB51B (io), U17 PB57B (io), V13 PB38B/D3/SPID4 (io), V14 PB40B/D5/SPID2 (io), V15 PB44A (io), V16 PB51A (io), V17 PB52B (io), W12 PB35A/VREF1_4 (io), W13 PB36A/VREF2_4 (io), W14 PB39A (io), W15 PB43B (io), W16 PB50A (io), W17 PB54B (io), W18 PB56B (io), Y12 PB34A/WRITEN (io), Y13 PB40A (io), Y14 PB42B (io), Y15 PB43A (io), Y16 PB54A/BDQS54 (io), Y17 PB52A (io), Y18 PB56A (io), Y19 PB55B (io)
part F pins: AA3 PB13A (io), AA4 PB17A (io), AA5 PB15A (io), AA6 PB25A (io), AA7 PB26B (io), AA8 PB26A (io), AA9 PB30B (io), AA10 PB30A/BDQS30 (io), AA11 PB31B (io), AB3 PB13B (io), AB4 PB17B (io), AB5 PB25B (io), AB6 PB27A (io), AB7 PB27B (io), AB8 PB29A (io), AB9 PB29B (io), AB10 PB33A/PCLKT5_0 (io), AB11 PB33B/PCLKC5_0 (io), T6 PB10B (io), T9 PB22B (io), T10 PB24B (io), U6 PB12B (io), U7 PB11B (io), U8 PB19B (io), U9 PB20B (io), U10 PB23B (io), V6 PB14B (io), V7 PB10A (io), V8 PB11A (io), V9 PB22A/BDQS22 (io), V10 PB24A (io), V11 PB32A/VREF2_5 (io), V12 PB32B/VREF1_5 (io), W5 PB12A (io), W6 PB15B (io), W7 PB19A (io), W8 PB18B (io), W9 PB20A (io), W10 PB23A (io), W11 PB28B (io), Y4 PB16B (io), Y5 PB16A (io), Y6 PB14A/BDQS14 (io), Y7 PB18A (io), Y8 PB21A (io), Y9 PB21B (io), Y10 PB28A (io), Y11 PB31A (io)
part G pins: AA1 PL58A (io), AA2 PL58B (io), L1 PL37B (io), L2 PL37A (io), L4 PL36A (io), L5 PL36B (io), M1 PL39A (io), M2 PL39B (io), M3 PL40B (io), M4 PL38A (io), M5 PL38B (io), N1 PL42A (io), N2 PL42B (io), N3 PL40A/LDQS40 (io), N4 PL41B (io), N5 PL41A (io), P1 PL43A (io), P2 PL43B (io), P3 PL45A (io), P4 PL45B (io), P5 PL44B (io), R1 PL46A (io), R2 PL46B (io), R3 PL49A (io), R4 PL47B (io), R5 PL47A (io), R6 PL44A (io), T1 PL48A/LDQS48 (io), T2 PL48B (io), T3 PL49B (io), U3 PL54A/LLM0_PLLT_FB_A (io), U4 PL55A (io), V1 PL53A/LLM0_PLLT_IN_A (io), V2 PL53B/LLM0_PLLC_IN_A (io), V3 PL54B/LLM0_PLLC_FB_A (io), V4 PL59B (io), V5 PL55B (io), W1 PL56A (io), W2 PL56B (io), W3 PL68A/VREF1_6 (io), W4 PL59A (io), Y1 PL57A/LDQS57 (io), Y2 PL57B (io), Y3 PL68B/VREF2_6 (io)
part H pins: B1 PL16A/LUM0_PLLT_IN_A (io), B2 PL10B (io), C1 PL16B/LUM0_PLLC_IN_A (io), C2 PL12B (io), C3 PL10A (io), D1 PL27B (io), D2 PL15B (io), D3 PL12A (io), D4 PL2A/VREF2_7 (io), E1 PL27A (io), E2 PL17B/LUM0_PLLC_FB_A (io), E3 PL15A (io), E4 PL2B/VREF1_7 (io), E5 PL11A (io), F1 PL26B (io), F2 PL26A (io), F3 PL17A/LUM0_PLLT_FB_A (io), F4 PL14A/LDQS14 (io), F5 PL11B (io), G1 PL29B (io), G2 PL28B (io), G3 PL24A (io), G4 PL14B (io), G5 PL23A/LDQS23 (io), H1 PL31B (io), H2 PL29A (io), H3 PL28A (io), H4 PL24B (io), H5 PL25B (io), H6 PL23B (io), J1 PL34A/PCLKT7_0 (io), J2 PL31A/LDQS31 (io), J3 PL30B (io), J4 PL30A (io), J5 PL25A (io), K1 PL34B/PCLKC7_0 (io), K2 PL33B (io), K3 PL33A (io), K4 PL32A (io), K5 PL32B (io)
part I pins: L3 XRES, R20 DONE (io), T4 TMS (in), T5 TCK (in), T19 CFG2 (in), T20 CCLK (io), T21 INITN (io), U1 TDO (out), U5 TDI (in), U18 CFG0 (in), U19 CFG1 (in)
part J pins: G7 VCCAUX (power), G8 VCCAUX (power), G11 VCCIO0 (power), G12 VCCIO1 (power), G15 VCCAUX (power), G16 VCCAUX (power), H7 VCCAUX (power), H9 VCCIO0 (power), H10 VCCIO0 (power), H11 VCCIO0 (power), H12 VCCIO1 (power), H13 VCCIO1 (power), H14 VCCIO1 (power), H16 VCCAUX (power), J7 VCC (power), J8 VCCIO7 (power), J15 VCCIO2 (power), J16 VCC (power), K6 VCC (power), K7 VCC (power), K8 VCCIO7 (power), K15 VCCIO2 (power), K16 VCC (power), K17 VCC (power), L6 VCC (power), L7 VCCIO7 (power), L8 VCCIO7 (power), L15 VCCIO2 (power), L16 VCCIO2 (power), L17 VCC (power), M6 VCC (power), M7 VCCIO6 (power), M8 VCCIO6 (power), M15 VCCIO3 (power), M16 VCCIO3 (power), M17 VCC (power), N6 VCC (power), N7 VCC (power), N8 VCCIO6 (power), N15 VCCIO3 (power), N16 VCC (power), N17 VCC (power), P7 VCC (power), P8 VCCIO6 (power), P15 VCCIO3 (power), P16 VCC (power), R7 VCCAUX (power), R9 VCCIO5 (power), R10 VCCIO5 (power), R11 VCCIO5 (power), R12 VCCIO4 (power), R13 VCCIO4 (power), R14 VCCIO4 (power), R16 VCCAUX (power), T7 VCCAUX (power), T8 VCCAUX (power), T11 VCCIO5 (power), T12 VCCIO4 (power), T15 VCCAUX (power), T16 VCCAUX (power), U2 VCCJ (power)
part K pins: A1 GND (power), A22 GND (power), AB1 GND (power), AB22 GND (power), H8 GND (power), H15 GND (power), J9 GND (power), J10 GND (power), J11 GND (power), J12 GND (power), J13 GND (power), J14 GND (power), K9 GND (power), K10 GND (power), K11 GND (power), K12 GND (power), K13 GND (power), K14 GND (power), L9 GND (power), L10 GND (power), L11 GND (power), L12 GND (power), L13 GND (power), L14 GND (power), M9 GND (power), M10 GND (power), M11 GND (power), M12 GND (power), M13 GND (power), M14 GND (power), N9 GND (power), N10 GND (power), N11 GND (power), N12 GND (power), N13 GND (power), N14 GND (power), P9 GND (power), P10 GND (power), P11 GND (power), P12 GND (power), P13 GND (power), P14 GND (power), R8 GND (power), R15 GND (power)
part L pins: J6 VCCPLL (power), J17 VCCPLL (power), P6 VCCPLL (power), P17 VCCPLL (power)
part M pins: A2 NC, A21 NC, AB2 NC

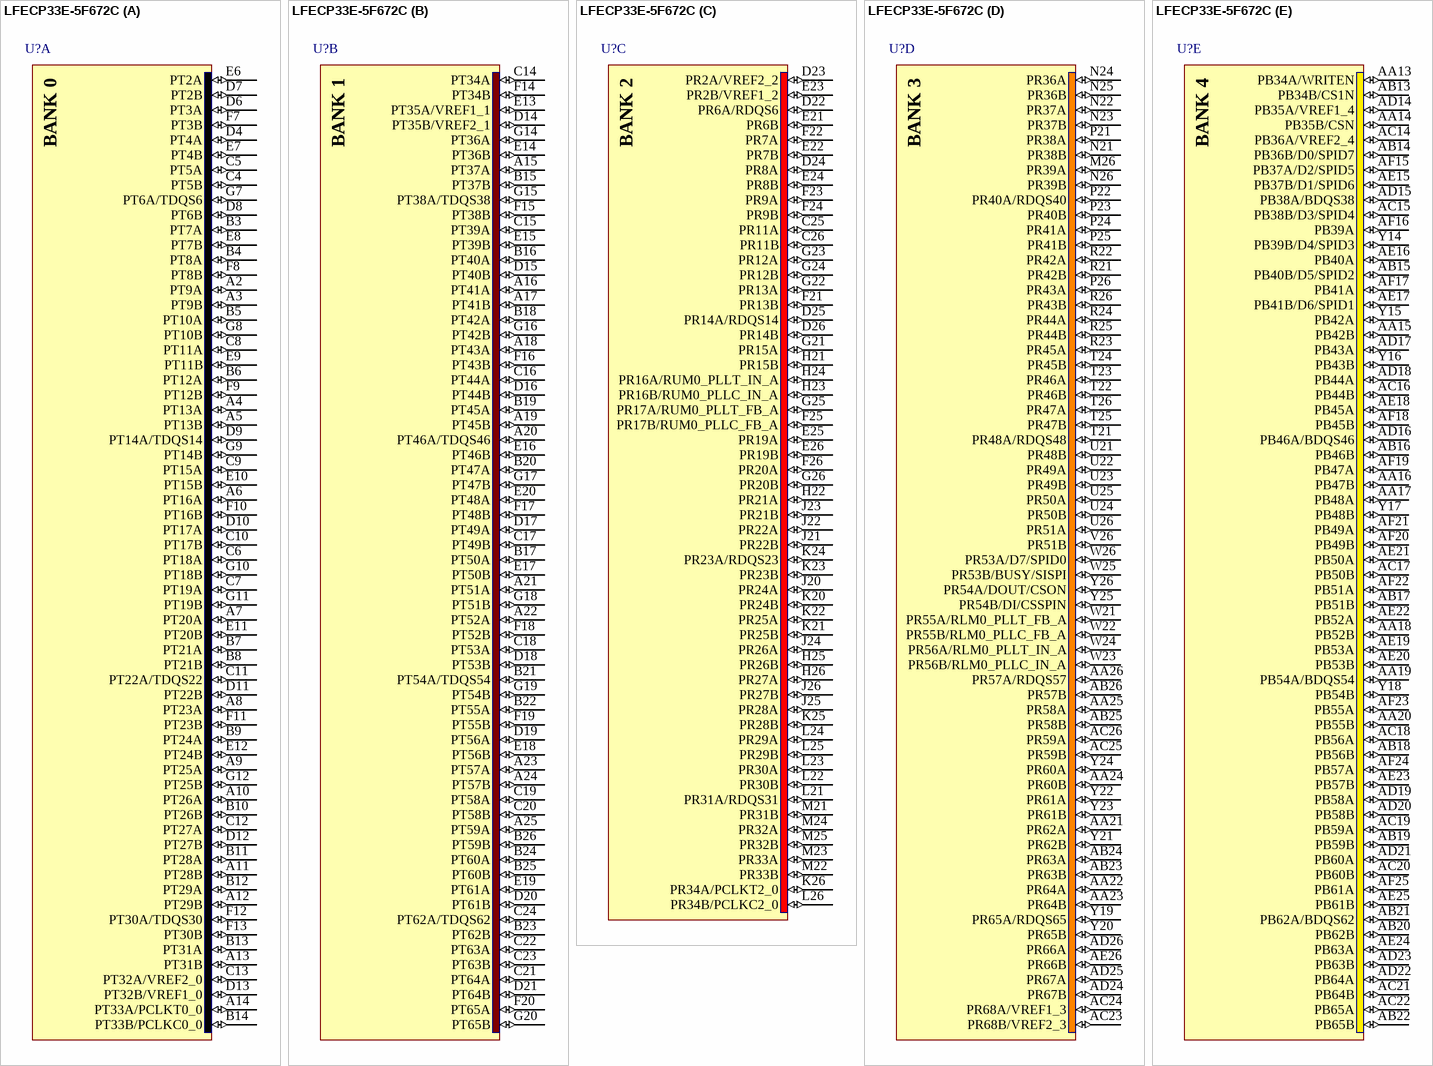
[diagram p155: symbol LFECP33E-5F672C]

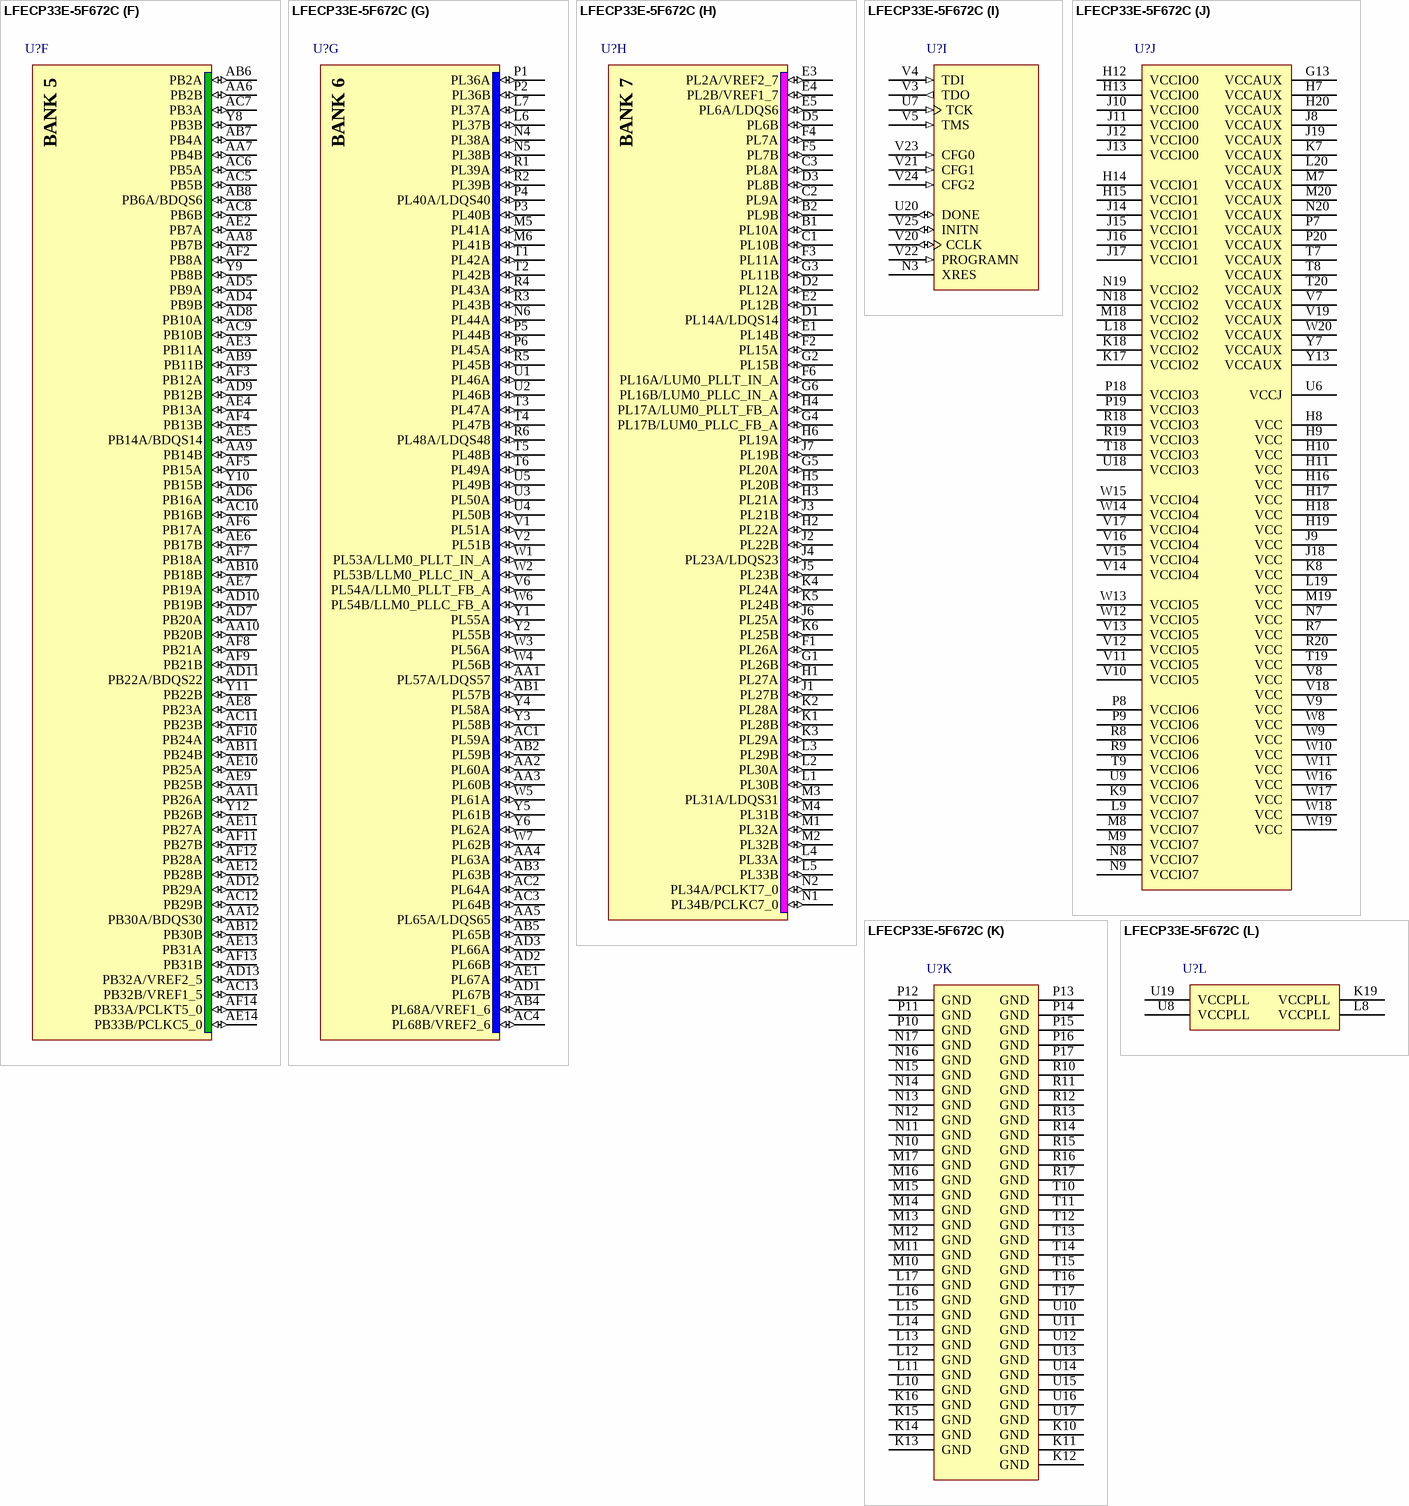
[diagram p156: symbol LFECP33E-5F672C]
